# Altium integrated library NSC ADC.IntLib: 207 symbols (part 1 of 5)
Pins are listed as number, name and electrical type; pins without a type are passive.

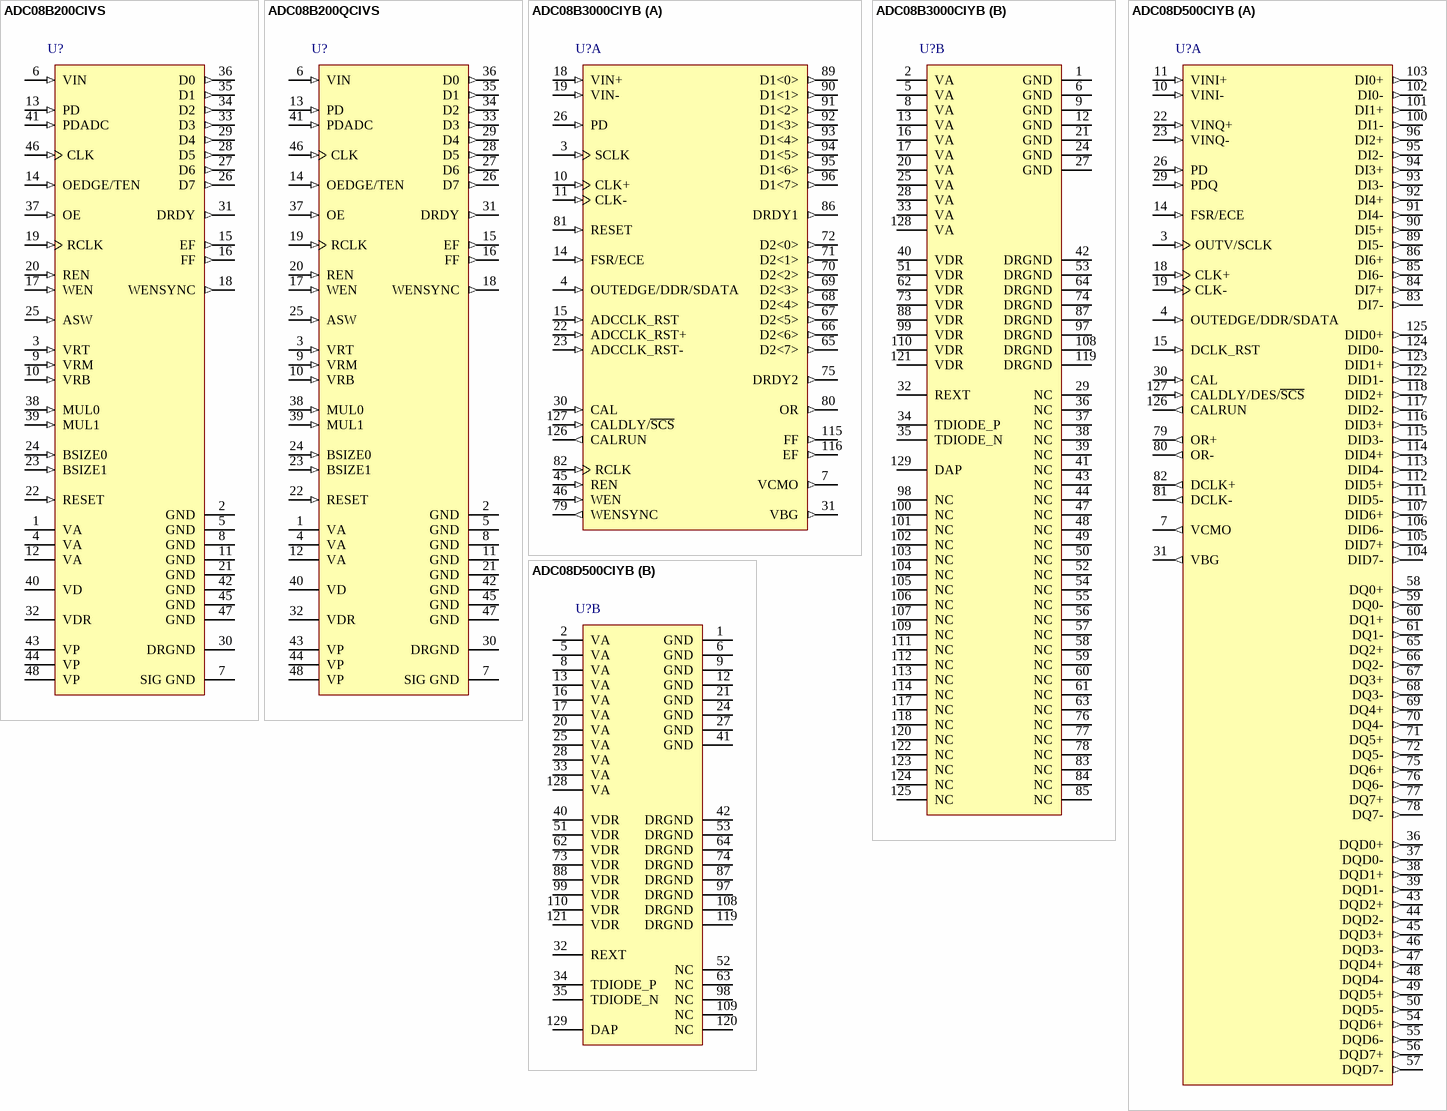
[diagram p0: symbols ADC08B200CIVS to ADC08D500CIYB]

## ADC08B200CIVS
designator U?
8-Bit, 200 MSPS A/D Converter with Capture Buffer; PartNumber: ADC08B200CIVS; Manufacturer: National Semiconductor; CompType: ADC IC; PackageTopMarking: NSUZXYTT*DC08B200*CIVS; PowerWise: N
footprint VBC48A_N (Thin QFP, 48-Leads, Body 7x7mm, Pitch 0.5mm, IPC Medium Density)
footprint VBC48A_L (Thin QFP, 48-Leads, Body 7x7mm, Pitch 0.5mm, IPC High Density)
footprint VBC48A_M (Thin QFP, 48-Leads, Body 7x7mm, Pitch 0.5mm, IPC Low Density)
pins: 1 VA (power), 2 GND (power), 3 VRT (in), 4 VA (power), 5 GND (power), 6 VIN (in), 7 SIG GND (power), 8 GND (power), 9 VRM (in), 10 VRB (in), 11 GND (power), 12 VA (power), 13 PD (in), 14 OEDGE/TEN (in), 15 EF (out), 16 FF (out), 17 WEN (in), 18 WENSYNC (out), 19 RCLK (in), 20 REN (in), 21 GND (power), 22 RESET (in), 23 BSIZE1 (in), 24 BSIZE0 (in), 25 ASW (in), 26 D7 (out), 27 D6 (out), 28 D5 (out), 29 D4 (out), 30 DRGND (power), 31 DRDY (out), 32 VDR (power), 33 D3 (out), 34 D2 (out), 35 D1 (out), 36 D0 (out), 37 OE (in), 38 MUL0 (in), 39 MUL1 (in), 40 VD (power), 41 PDADC (in), 42 GND (power), 43 VP (power), 44 VP (power), 45 GND (power), 46 CLK (in), 47 GND (power), 48 VP (power)

## ADC08B200QCIVS
designator U?
8-Bit, 200 MSPS A/D Converter with Capture Buffer; PartNumber: ADC08B200QCIVS; Manufacturer: National Semiconductor; CompType: ADC IC; PackageTopMarking: NSUZXYTT*DC08B200*QCIVS; PowerWise: N
footprint VBC48A_N (Thin QFP, 48-Leads, Body 7x7mm, Pitch 0.5mm, IPC Medium Density)
footprint VBC48A_L (Thin QFP, 48-Leads, Body 7x7mm, Pitch 0.5mm, IPC High Density)
footprint VBC48A_M (Thin QFP, 48-Leads, Body 7x7mm, Pitch 0.5mm, IPC Low Density)
pins: 1 VA (power), 2 GND (power), 3 VRT (in), 4 VA (power), 5 GND (power), 6 VIN (in), 7 SIG GND (power), 8 GND (power), 9 VRM (in), 10 VRB (in), 11 GND (power), 12 VA (power), 13 PD (in), 14 OEDGE/TEN (in), 15 EF (out), 16 FF (out), 17 WEN (in), 18 WENSYNC (out), 19 RCLK (in), 20 REN (in), 21 GND (power), 22 RESET (in), 23 BSIZE1 (in), 24 BSIZE0 (in), 25 ASW (in), 26 D7 (out), 27 D6 (out), 28 D5 (out), 29 D4 (out), 30 DRGND (power), 31 DRDY (out), 32 VDR (power), 33 D3 (out), 34 D2 (out), 35 D1 (out), 36 D0 (out), 37 OE (in), 38 MUL0 (in), 39 MUL1 (in), 40 VD (power), 41 PDADC (in), 42 GND (power), 43 VP (power), 44 VP (power), 45 GND (power), 46 CLK (in), 47 GND (power), 48 VP (power)

## ADC08B3000CIYB
designator U?
8-Bit, 3 GSPS, High Performance, Low Power A/D Converter with 4K Buffer; PartNumber: ADC08B3000CIYB; Manufacturer: National Semiconductor; CompType: ADC IC; PackageTopMarking: NSUZXYYTTE#*ADC08B3000*CIYB; PowerWise: Y
footprint VNX128A_N (Thin QFP, 128-Leads, Body 20x20mm, Pitch 0.5mm, Exposed Pad, IPC Medium Density)
footprint VNX128A_L (Thin QFP, 128-Leads, Body 20x20mm, Pitch 0.5mm, Exposed Pad, IPC High Density)
footprint VNX128A_M (Thin QFP, 128-Leads, Body 20x20mm, Pitch 0.5mm, Exposed Pad, IPC Low Density)
part A pins: 3 SCLK (in), 4 OUTEDGE/DDR/SDATA (in), 7 VCMO (out), 10 CLK+ (in), 11 CLK- (in), 14 FSR/ECE (in), 15 ADCCLK_RST (in), 18 VIN+ (in), 19 VIN- (in), 22 ADCCLK_RST+ (in), 23 ADCCLK_RST- (in), 26 PD (in), 30 CAL (in), 31 VBG (out), 45 REN (in), 46 WEN (in), 65 D2<7> (out), 66 D2<6> (out), 67 D2<5> (out), 68 D2<4> (out), 69 D2<3> (out), 70 D2<2> (out), 71 D2<1> (out), 72 D2<0> (out), 75 DRDY2 (out), 79 WENSYNC (out), 80 OR (out), 81 RESET (in), 82 RCLK (in), 86 DRDY1 (out), 89 D1<0> (out), 90 D1<1> (out), 91 D1<2> (out), 92 D1<3> (out), 93 D1<4> (out), 94 D1<5> (out), 95 D1<6> (out), 96 D1<7> (out), 115 FF (out), 116 EF (out), 126 CALRUN (out), 127 CALDLY/~{SCS} (in)
part B pins: 1 GND (power), 2 VA (power), 5 VA (power), 6 GND (power), 8 VA (power), 9 GND (power), 12 GND (power), 13 VA (power), 16 VA (power), 17 VA (power), 20 VA (power), 21 GND (power), 24 GND (power), 25 VA (power), 27 GND (power), 28 VA (power), 29 NC, 32 REXT, 33 VA (power), 34 TDIODE_P, 35 TDIODE_N, 36 NC, 37 NC, 38 NC, 39 NC, 40 VDR (power), 41 NC, 42 DRGND (power), 43 NC, 44 NC, 47 NC, 48 NC, 49 NC, 50 NC, 51 VDR (power), 52 NC, 53 DRGND (power), 54 NC, 55 NC, 56 NC, 57 NC, 58 NC, 59 NC, 60 NC, 61 NC, 62 VDR (power), 63 NC, 64 DRGND (power), 73 VDR (power), 74 DRGND (power), 76 NC, 77 NC, 78 NC, 83 NC, 84 NC, 85 NC, 87 DRGND (power), 88 VDR (power), 97 DRGND (power), 98 NC, 99 VDR (power), 100 NC, 101 NC, 102 NC, 103 NC, 104 NC, 105 NC, 106 NC, 107 NC, 108 DRGND (power), 109 NC, 110 VDR (power), 111 NC, 112 NC, 113 NC, 114 NC, 117 NC, 118 NC, 119 DRGND (power), 120 NC, 121 VDR (power), 122 NC, 123 NC, 124 NC, 125 NC, 128 VA (power), 129 DAP (power)

## ADC08D500CIYB
designator U?
High Performance, Low Power, Dual 8-Bit, 500 MSPS A/D Converter; PartNumber: ADC08D500CIYB; Manufacturer: National Semiconductor; CompType: ADC IC; PackageTopMarking: NSUZXYYTTE#*ADC08D500*CIYB; PowerWise: Y
footprint VNX128A_N (Thin QFP, 128-Leads, Body 20x20mm, Pitch 0.5mm, Exposed Pad, IPC Medium Density)
footprint VNX128A_L (Thin QFP, 128-Leads, Body 20x20mm, Pitch 0.5mm, Exposed Pad, IPC High Density)
footprint VNX128A_M (Thin QFP, 128-Leads, Body 20x20mm, Pitch 0.5mm, Exposed Pad, IPC Low Density)
part A pins: 3 OUTV/SCLK (in), 4 OUTEDGE/DDR/SDATA (in), 7 VCMO (out), 10 VINI- (in), 11 VINI+ (in), 14 FSR/ECE (in), 15 DCLK_RST (in), 18 CLK+ (in), 19 CLK- (in), 22 VINQ+ (in), 23 VINQ- (in), 26 PD (in), 29 PDQ (in), 30 CAL (in), 31 VBG (out), 36 DQD0+ (out), 37 DQD0- (out), 38 DQD1+ (out), 39 DQD1- (out), 43 DQD2+ (out), 44 DQD2- (out), 45 DQD3+ (out), 46 DQD3- (out), 47 DQD4+ (out), 48 DQD4- (out), 49 DQD5+ (out), 50 DQD5- (out), 54 DQD6+ (out), 55 DQD6- (out), 56 DQD7+ (out), 57 DQD7- (out), 58 DQ0+ (out), 59 DQ0- (out), 60 DQ1+ (out), 61 DQ1- (out), 65 DQ2+ (out), 66 DQ2- (out), 67 DQ3+ (out), 68 DQ3- (out), 69 DQ4+ (out), 70 DQ4- (out), 71 DQ5+ (out), 72 DQ5- (out), 75 DQ6+ (out), 76 DQ6- (out), 77 DQ7+ (out), 78 DQ7- (out), 79 OR+ (out), 80 OR- (out), 81 DCLK- (out), 82 DCLK+ (out), 83 DI7- (out), 84 DI7+ (out), 85 DI6- (out), 86 DI6+ (out), 89 DI5- (out), 90 DI5+ (out), 91 DI4- (out), 92 DI4+ (out), 93 DI3- (out), 94 DI3+ (out), 95 DI2- (out), 96 DI2+ (out), 100 DI1- (out), 101 DI1+ (out), 102 DI0- (out), 103 DI0+ (out), 104 DID7- (out), 105 DID7+ (out), 106 DID6- (out), 107 DID6+ (out), 111 DID5- (out), 112 DID5+ (out), 113 DID4- (out), 114 DID4+ (out), 115 DID3- (out), 116 DID3+ (out), 117 DID2- (out), 118 DID2+ (out), 122 DID1- (out), 123 DID1+ (out), 124 DID0- (out), 125 DID0+ (out), 126 CALRUN (out), 127 CALDLY/DES/~{SCS} (in)
part B pins: 1 GND (power), 2 VA (power), 5 VA (power), 6 GND (power), 8 VA (power), 9 GND (power), 12 GND (power), 13 VA (power), 16 VA (power), 17 VA (power), 20 VA (power), 21 GND (power), 24 GND (power), 25 VA (power), 27 GND (power), 28 VA (power), 32 REXT, 33 VA (power), 34 TDIODE_P, 35 TDIODE_N, 40 VDR (power), 41 GND (power), 42 DRGND (power), 51 VDR (power), 52 NC, 53 DRGND (power), 62 VDR (power), 63 NC, 64 DRGND (power), 73 VDR (power), 74 DRGND (power), 87 DRGND (power), 88 VDR (power), 97 DRGND (power), 98 NC, 99 VDR (power), 108 DRGND (power), 109 NC, 110 VDR (power), 119 DRGND (power), 120 NC, 121 VDR (power), 128 VA (power), 129 DAP (power)

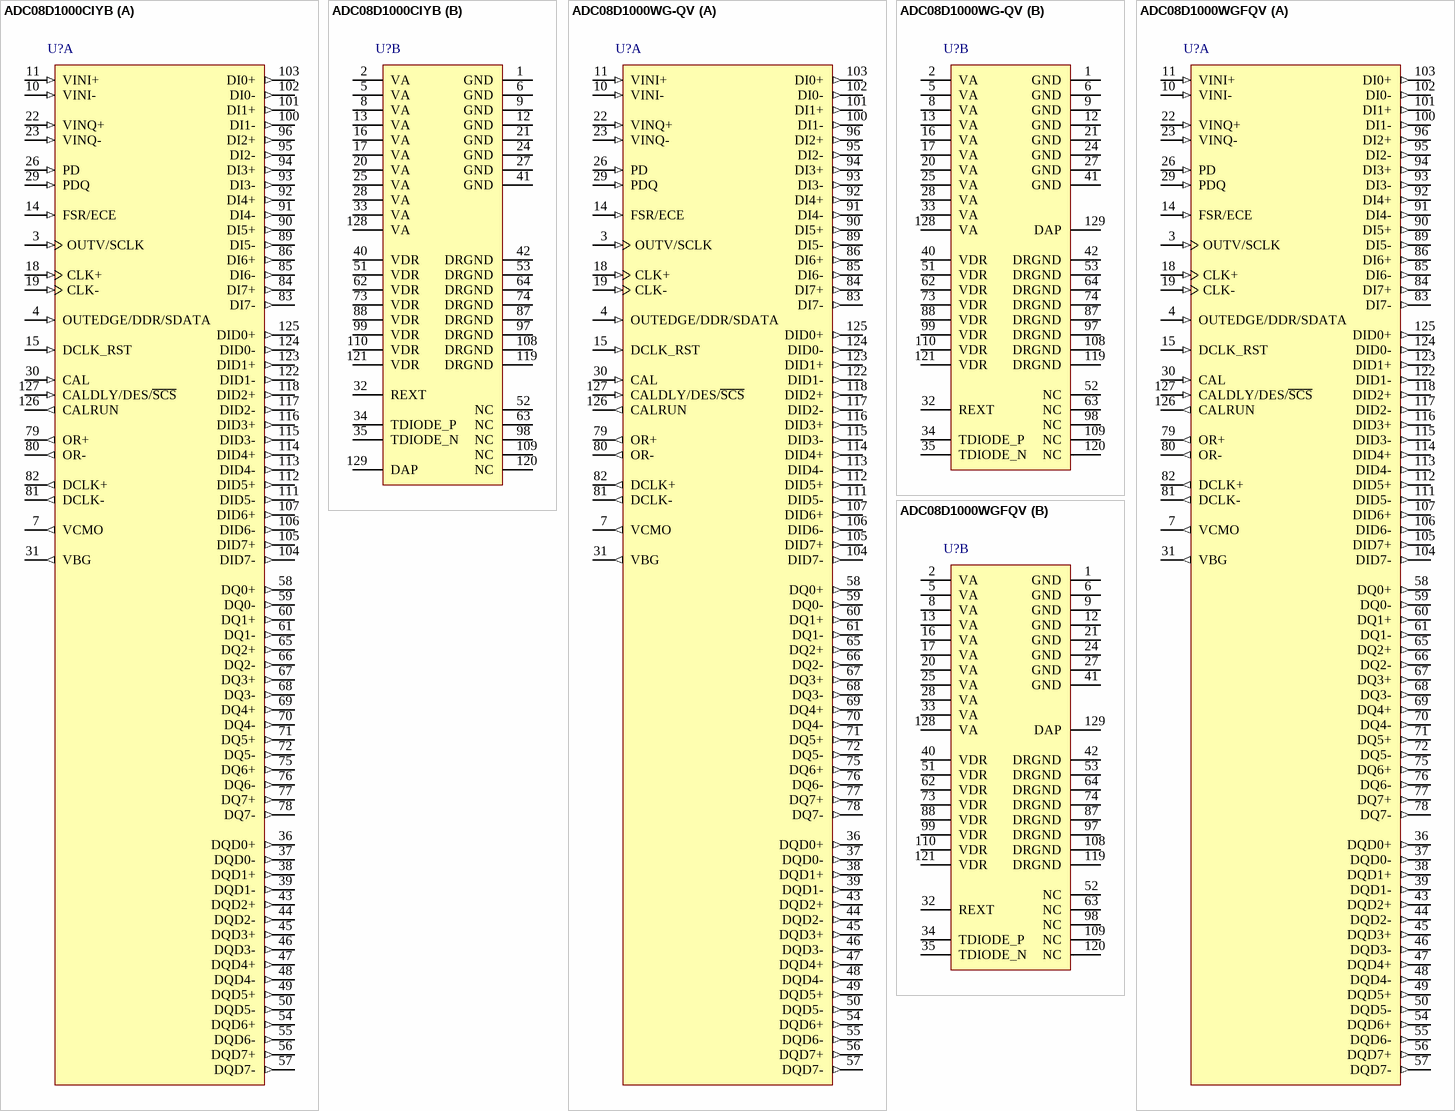
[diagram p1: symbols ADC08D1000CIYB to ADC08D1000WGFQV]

## ADC08D1000CIYB
designator U?
High Performance, Low Power, Dual 8-Bit, 1 GSPS A/D Converter; PartNumber: ADC08D1000CIYB; Manufacturer: National Semiconductor; CompType: ADC IC; PackageTopMarking: NSUZXYYTTE#*ADC08D1000*CIYB; PowerWise: Y
footprint VNX128A_N (Thin QFP, 128-Leads, Body 20x20mm, Pitch 0.5mm, Exposed Pad, IPC Medium Density)
footprint VNX128A_L (Thin QFP, 128-Leads, Body 20x20mm, Pitch 0.5mm, Exposed Pad, IPC High Density)
footprint VNX128A_M (Thin QFP, 128-Leads, Body 20x20mm, Pitch 0.5mm, Exposed Pad, IPC Low Density)
part A pins: 3 OUTV/SCLK (in), 4 OUTEDGE/DDR/SDATA (in), 7 VCMO (out), 10 VINI- (in), 11 VINI+ (in), 14 FSR/ECE (in), 15 DCLK_RST (in), 18 CLK+ (in), 19 CLK- (in), 22 VINQ+ (in), 23 VINQ- (in), 26 PD (in), 29 PDQ (in), 30 CAL (in), 31 VBG (out), 36 DQD0+ (out), 37 DQD0- (out), 38 DQD1+ (out), 39 DQD1- (out), 43 DQD2+ (out), 44 DQD2- (out), 45 DQD3+ (out), 46 DQD3- (out), 47 DQD4+ (out), 48 DQD4- (out), 49 DQD5+ (out), 50 DQD5- (out), 54 DQD6+ (out), 55 DQD6- (out), 56 DQD7+ (out), 57 DQD7- (out), 58 DQ0+ (out), 59 DQ0- (out), 60 DQ1+ (out), 61 DQ1- (out), 65 DQ2+ (out), 66 DQ2- (out), 67 DQ3+ (out), 68 DQ3- (out), 69 DQ4+ (out), 70 DQ4- (out), 71 DQ5+ (out), 72 DQ5- (out), 75 DQ6+ (out), 76 DQ6- (out), 77 DQ7+ (out), 78 DQ7- (out), 79 OR+ (out), 80 OR- (out), 81 DCLK- (out), 82 DCLK+ (out), 83 DI7- (out), 84 DI7+ (out), 85 DI6- (out), 86 DI6+ (out), 89 DI5- (out), 90 DI5+ (out), 91 DI4- (out), 92 DI4+ (out), 93 DI3- (out), 94 DI3+ (out), 95 DI2- (out), 96 DI2+ (out), 100 DI1- (out), 101 DI1+ (out), 102 DI0- (out), 103 DI0+ (out), 104 DID7- (out), 105 DID7+ (out), 106 DID6- (out), 107 DID6+ (out), 111 DID5- (out), 112 DID5+ (out), 113 DID4- (out), 114 DID4+ (out), 115 DID3- (out), 116 DID3+ (out), 117 DID2- (out), 118 DID2+ (out), 122 DID1- (out), 123 DID1+ (out), 124 DID0- (out), 125 DID0+ (out), 126 CALRUN (out), 127 CALDLY/DES/~{SCS} (in)
part B pins: 1 GND (power), 2 VA (power), 5 VA (power), 6 GND (power), 8 VA (power), 9 GND (power), 12 GND (power), 13 VA (power), 16 VA (power), 17 VA (power), 20 VA (power), 21 GND (power), 24 GND (power), 25 VA (power), 27 GND (power), 28 VA (power), 32 REXT, 33 VA (power), 34 TDIODE_P, 35 TDIODE_N, 40 VDR (power), 41 GND (power), 42 DRGND (power), 51 VDR (power), 52 NC, 53 DRGND (power), 62 VDR (power), 63 NC, 64 DRGND (power), 73 VDR (power), 74 DRGND (power), 87 DRGND (power), 88 VDR (power), 97 DRGND (power), 98 NC, 99 VDR (power), 108 DRGND (power), 109 NC, 110 VDR (power), 119 DRGND (power), 120 NC, 121 VDR (power), 128 VA (power), 129 DAP (power)

## ADC08D1000WG-QV
designator U?
High Performance, Low Power, Dual 8-Bit, 1 GSPS A/D Converter; PartNumber: ADC08D1000WG-QV; Manufacturer: National Semiconductor; CompType: ADC IC; PackageTopMarking: NSZSSXXYYA*ADC08D1000*WG-QV 5962-*0520601VZC Q; PowerWise: N
footprint EM128A_N (CQFP, 128-Leads, Body 19.6x19.6mm; Pitch 0.508mm, Gullwing Leadform, IPC Medium Density)
footprint EM128A_L (CQFP, 128-Leads, Body 19.6x19.6mm; Pitch 0.508mm, Gullwing Leadform, IPC High Density)
footprint EM128A_M (CQFP, 128-Leads, Body 19.6x19.6mm; Pitch 0.508mm, Gullwing Leadform, IPC Low Density)
part A pins: 3 OUTV/SCLK (in), 4 OUTEDGE/DDR/SDATA (in), 7 VCMO (out), 10 VINI- (in), 11 VINI+ (in), 14 FSR/ECE (in), 15 DCLK_RST (in), 18 CLK+ (in), 19 CLK- (in), 22 VINQ+ (in), 23 VINQ- (in), 26 PD (in), 29 PDQ (in), 30 CAL (in), 31 VBG (out), 36 DQD0+ (out), 37 DQD0- (out), 38 DQD1+ (out), 39 DQD1- (out), 43 DQD2+ (out), 44 DQD2- (out), 45 DQD3+ (out), 46 DQD3- (out), 47 DQD4+ (out), 48 DQD4- (out), 49 DQD5+ (out), 50 DQD5- (out), 54 DQD6+ (out), 55 DQD6- (out), 56 DQD7+ (out), 57 DQD7- (out), 58 DQ0+ (out), 59 DQ0- (out), 60 DQ1+ (out), 61 DQ1- (out), 65 DQ2+ (out), 66 DQ2- (out), 67 DQ3+ (out), 68 DQ3- (out), 69 DQ4+ (out), 70 DQ4- (out), 71 DQ5+ (out), 72 DQ5- (out), 75 DQ6+ (out), 76 DQ6- (out), 77 DQ7+ (out), 78 DQ7- (out), 79 OR+ (out), 80 OR- (out), 81 DCLK- (out), 82 DCLK+ (out), 83 DI7- (out), 84 DI7+ (out), 85 DI6- (out), 86 DI6+ (out), 89 DI5- (out), 90 DI5+ (out), 91 DI4- (out), 92 DI4+ (out), 93 DI3- (out), 94 DI3+ (out), 95 DI2- (out), 96 DI2+ (out), 100 DI1- (out), 101 DI1+ (out), 102 DI0- (out), 103 DI0+ (out), 104 DID7- (out), 105 DID7+ (out), 106 DID6- (out), 107 DID6+ (out), 111 DID5- (out), 112 DID5+ (out), 113 DID4- (out), 114 DID4+ (out), 115 DID3- (out), 116 DID3+ (out), 117 DID2- (out), 118 DID2+ (out), 122 DID1- (out), 123 DID1+ (out), 124 DID0- (out), 125 DID0+ (out), 126 CALRUN (out), 127 CALDLY/DES/~{SCS} (in)
part B pins: 1 GND (power), 2 VA (power), 5 VA (power), 6 GND (power), 8 VA (power), 9 GND (power), 12 GND (power), 13 VA (power), 16 VA (power), 17 VA (power), 20 VA (power), 21 GND (power), 24 GND (power), 25 VA (power), 27 GND (power), 28 VA (power), 32 REXT, 33 VA (power), 34 TDIODE_P, 35 TDIODE_N, 40 VDR (power), 41 GND (power), 42 DRGND (power), 51 VDR (power), 52 NC, 53 DRGND (power), 62 VDR (power), 63 NC, 64 DRGND (power), 73 VDR (power), 74 DRGND (power), 87 DRGND (power), 88 VDR (power), 97 DRGND (power), 98 NC, 99 VDR (power), 108 DRGND (power), 109 NC, 110 VDR (power), 119 DRGND (power), 120 NC, 121 VDR (power), 128 VA (power), 129 DAP (power)

## ADC08D1000WGFQV
designator U?
High Performance, Low Power, Dual 8-Bit, 1 GSPS A/D Converter; PartNumber: ADC08D1000WGFQV; Manufacturer: National Semiconductor; CompType: ADC IC; PackageTopMarking: NSZSSXXYYA*ADC08D1000*WGFQV 5962F*0520601VZC Q; PowerWise: N
footprint EM128A_N (CQFP, 128-Leads, Body 19.6x19.6mm; Pitch 0.508mm, Gullwing Leadform, IPC Medium Density)
footprint EM128A_L (CQFP, 128-Leads, Body 19.6x19.6mm; Pitch 0.508mm, Gullwing Leadform, IPC High Density)
footprint EM128A_M (CQFP, 128-Leads, Body 19.6x19.6mm; Pitch 0.508mm, Gullwing Leadform, IPC Low Density)
part A pins: 3 OUTV/SCLK (in), 4 OUTEDGE/DDR/SDATA (in), 7 VCMO (out), 10 VINI- (in), 11 VINI+ (in), 14 FSR/ECE (in), 15 DCLK_RST (in), 18 CLK+ (in), 19 CLK- (in), 22 VINQ+ (in), 23 VINQ- (in), 26 PD (in), 29 PDQ (in), 30 CAL (in), 31 VBG (out), 36 DQD0+ (out), 37 DQD0- (out), 38 DQD1+ (out), 39 DQD1- (out), 43 DQD2+ (out), 44 DQD2- (out), 45 DQD3+ (out), 46 DQD3- (out), 47 DQD4+ (out), 48 DQD4- (out), 49 DQD5+ (out), 50 DQD5- (out), 54 DQD6+ (out), 55 DQD6- (out), 56 DQD7+ (out), 57 DQD7- (out), 58 DQ0+ (out), 59 DQ0- (out), 60 DQ1+ (out), 61 DQ1- (out), 65 DQ2+ (out), 66 DQ2- (out), 67 DQ3+ (out), 68 DQ3- (out), 69 DQ4+ (out), 70 DQ4- (out), 71 DQ5+ (out), 72 DQ5- (out), 75 DQ6+ (out), 76 DQ6- (out), 77 DQ7+ (out), 78 DQ7- (out), 79 OR+ (out), 80 OR- (out), 81 DCLK- (out), 82 DCLK+ (out), 83 DI7- (out), 84 DI7+ (out), 85 DI6- (out), 86 DI6+ (out), 89 DI5- (out), 90 DI5+ (out), 91 DI4- (out), 92 DI4+ (out), 93 DI3- (out), 94 DI3+ (out), 95 DI2- (out), 96 DI2+ (out), 100 DI1- (out), 101 DI1+ (out), 102 DI0- (out), 103 DI0+ (out), 104 DID7- (out), 105 DID7+ (out), 106 DID6- (out), 107 DID6+ (out), 111 DID5- (out), 112 DID5+ (out), 113 DID4- (out), 114 DID4+ (out), 115 DID3- (out), 116 DID3+ (out), 117 DID2- (out), 118 DID2+ (out), 122 DID1- (out), 123 DID1+ (out), 124 DID0- (out), 125 DID0+ (out), 126 CALRUN (out), 127 CALDLY/DES/~{SCS} (in)
part B pins: 1 GND (power), 2 VA (power), 5 VA (power), 6 GND (power), 8 VA (power), 9 GND (power), 12 GND (power), 13 VA (power), 16 VA (power), 17 VA (power), 20 VA (power), 21 GND (power), 24 GND (power), 25 VA (power), 27 GND (power), 28 VA (power), 32 REXT, 33 VA (power), 34 TDIODE_P, 35 TDIODE_N, 40 VDR (power), 41 GND (power), 42 DRGND (power), 51 VDR (power), 52 NC, 53 DRGND (power), 62 VDR (power), 63 NC, 64 DRGND (power), 73 VDR (power), 74 DRGND (power), 87 DRGND (power), 88 VDR (power), 97 DRGND (power), 98 NC, 99 VDR (power), 108 DRGND (power), 109 NC, 110 VDR (power), 119 DRGND (power), 120 NC, 121 VDR (power), 128 VA (power), 129 DAP (power)

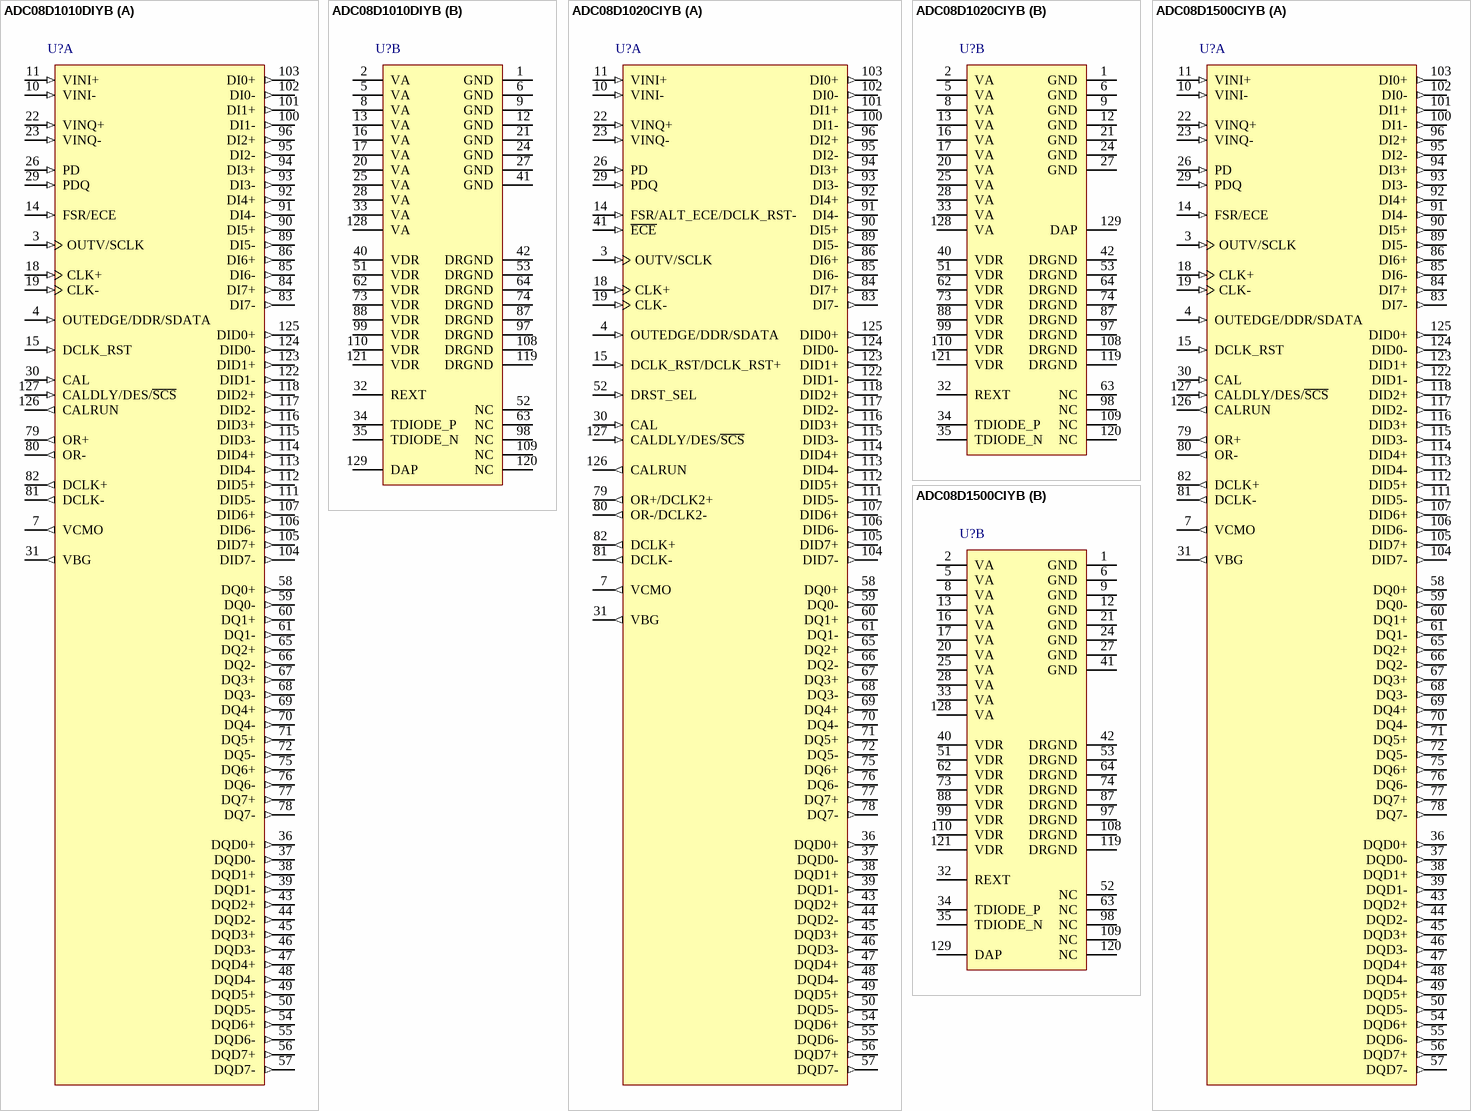
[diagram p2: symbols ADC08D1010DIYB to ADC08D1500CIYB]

## ADC08D1010DIYB
designator U?
High Performance, Low Power, Dual 8-Bit, 1 GSPS A/D Converter; PartNumber: ADC08D1010DIYB; Manufacturer: National Semiconductor; CompType: ADC IC; PackageTopMarking: NSUZXYYTTE#*ADC08D1010*DIYB
footprint VNX128A_N (Thin QFP, 128-Leads, Body 20x20mm, Pitch 0.5mm, Exposed Pad, IPC Medium Density)
footprint VNX128A_L (Thin QFP, 128-Leads, Body 20x20mm, Pitch 0.5mm, Exposed Pad, IPC High Density)
footprint VNX128A_M (Thin QFP, 128-Leads, Body 20x20mm, Pitch 0.5mm, Exposed Pad, IPC Low Density)
part A pins: 3 OUTV/SCLK (in), 4 OUTEDGE/DDR/SDATA (in), 7 VCMO (out), 10 VINI- (in), 11 VINI+ (in), 14 FSR/ECE (in), 15 DCLK_RST (in), 18 CLK+ (in), 19 CLK- (in), 22 VINQ+ (in), 23 VINQ- (in), 26 PD (in), 29 PDQ (in), 30 CAL (in), 31 VBG (out), 36 DQD0+ (out), 37 DQD0- (out), 38 DQD1+ (out), 39 DQD1- (out), 43 DQD2+ (out), 44 DQD2- (out), 45 DQD3+ (out), 46 DQD3- (out), 47 DQD4+ (out), 48 DQD4- (out), 49 DQD5+ (out), 50 DQD5- (out), 54 DQD6+ (out), 55 DQD6- (out), 56 DQD7+ (out), 57 DQD7- (out), 58 DQ0+ (out), 59 DQ0- (out), 60 DQ1+ (out), 61 DQ1- (out), 65 DQ2+ (out), 66 DQ2- (out), 67 DQ3+ (out), 68 DQ3- (out), 69 DQ4+ (out), 70 DQ4- (out), 71 DQ5+ (out), 72 DQ5- (out), 75 DQ6+ (out), 76 DQ6- (out), 77 DQ7+ (out), 78 DQ7- (out), 79 OR+ (out), 80 OR- (out), 81 DCLK- (out), 82 DCLK+ (out), 83 DI7- (out), 84 DI7+ (out), 85 DI6- (out), 86 DI6+ (out), 89 DI5- (out), 90 DI5+ (out), 91 DI4- (out), 92 DI4+ (out), 93 DI3- (out), 94 DI3+ (out), 95 DI2- (out), 96 DI2+ (out), 100 DI1- (out), 101 DI1+ (out), 102 DI0- (out), 103 DI0+ (out), 104 DID7- (out), 105 DID7+ (out), 106 DID6- (out), 107 DID6+ (out), 111 DID5- (out), 112 DID5+ (out), 113 DID4- (out), 114 DID4+ (out), 115 DID3- (out), 116 DID3+ (out), 117 DID2- (out), 118 DID2+ (out), 122 DID1- (out), 123 DID1+ (out), 124 DID0- (out), 125 DID0+ (out), 126 CALRUN (out), 127 CALDLY/DES/~{SCS} (in)
part B pins: 1 GND (power), 2 VA (power), 5 VA (power), 6 GND (power), 8 VA (power), 9 GND (power), 12 GND (power), 13 VA (power), 16 VA (power), 17 VA (power), 20 VA (power), 21 GND (power), 24 GND (power), 25 VA (power), 27 GND (power), 28 VA (power), 32 REXT, 33 VA (power), 34 TDIODE_P, 35 TDIODE_N, 40 VDR (power), 41 GND (power), 42 DRGND (power), 51 VDR (power), 52 NC, 53 DRGND (power), 62 VDR (power), 63 NC, 64 DRGND (power), 73 VDR (power), 74 DRGND (power), 87 DRGND (power), 88 VDR (power), 97 DRGND (power), 98 NC, 99 VDR (power), 108 DRGND (power), 109 NC, 110 VDR (power), 119 DRGND (power), 120 NC, 121 VDR (power), 128 VA (power), 129 DAP (power)

## ADC08D1020CIYB
designator U?
Low Power, Dual 8-Bit, 1.0 GSPS A/D Converter; PartNumber: ADC08D1020CIYB; Manufacturer: National Semiconductor; CompType: ADC IC; PackageTopMarking: NSUZXYYTTE#*ADC08D1020*CIYB; PowerWise: Y
footprint VNX128A_N (Thin QFP, 128-Leads, Body 20x20mm, Pitch 0.5mm, Exposed Pad, IPC Medium Density)
footprint VNX128A_L (Thin QFP, 128-Leads, Body 20x20mm, Pitch 0.5mm, Exposed Pad, IPC High Density)
footprint VNX128A_M (Thin QFP, 128-Leads, Body 20x20mm, Pitch 0.5mm, Exposed Pad, IPC Low Density)
part A pins: 3 OUTV/SCLK (in), 4 OUTEDGE/DDR/SDATA (in), 7 VCMO (out), 10 VINI- (in), 11 VINI+ (in), 14 FSR/ALT_ECE/DCLK_RST- (in), 15 DCLK_RST/DCLK_RST+ (in), 18 CLK+ (in), 19 CLK- (in), 22 VINQ+ (in), 23 VINQ- (in), 26 PD (in), 29 PDQ (in), 30 CAL (in), 31 VBG (out), 36 DQD0+ (out), 37 DQD0- (out), 38 DQD1+ (out), 39 DQD1- (out), 41 ~{ECE} (in), 43 DQD2+ (out), 44 DQD2- (out), 45 DQD3+ (out), 46 DQD3- (out), 47 DQD4+ (out), 48 DQD4- (out), 49 DQD5+ (out), 50 DQD5- (out), 52 DRST_SEL (in), 54 DQD6+ (out), 55 DQD6- (out), 56 DQD7+ (out), 57 DQD7- (out), 58 DQ0+ (out), 59 DQ0- (out), 60 DQ1+ (out), 61 DQ1- (out), 65 DQ2+ (out), 66 DQ2- (out), 67 DQ3+ (out), 68 DQ3- (out), 69 DQ4+ (out), 70 DQ4- (out), 71 DQ5+ (out), 72 DQ5- (out), 75 DQ6+ (out), 76 DQ6- (out), 77 DQ7+ (out), 78 DQ7- (out), 79 OR+/DCLK2+ (out), 80 OR-/DCLK2- (out), 81 DCLK- (out), 82 DCLK+ (out), 83 DI7- (out), 84 DI7+ (out), 85 DI6- (out), 86 DI6+ (out), 89 DI5- (out), 90 DI5+ (out), 91 DI4- (out), 92 DI4+ (out), 93 DI3- (out), 94 DI3+ (out), 95 DI2- (out), 96 DI2+ (out), 100 DI1- (out), 101 DI1+ (out), 102 DI0- (out), 103 DI0+ (out), 104 DID7- (out), 105 DID7+ (out), 106 DID6- (out), 107 DID6+ (out), 111 DID5- (out), 112 DID5+ (out), 113 DID4- (out), 114 DID4+ (out), 115 DID3- (out), 116 DID3+ (out), 117 DID2- (out), 118 DID2+ (out), 122 DID1- (out), 123 DID1+ (out), 124 DID0- (out), 125 DID0+ (out), 126 CALRUN (out), 127 CALDLY/DES/~{SCS} (in)
part B pins: 1 GND (power), 2 VA (power), 5 VA (power), 6 GND (power), 8 VA (power), 9 GND (power), 12 GND (power), 13 VA (power), 16 VA (power), 17 VA (power), 20 VA (power), 21 GND (power), 24 GND (power), 25 VA (power), 27 GND (power), 28 VA (power), 32 REXT, 33 VA (power), 34 TDIODE_P, 35 TDIODE_N, 40 VDR (power), 42 DRGND (power), 51 VDR (power), 53 DRGND (power), 62 VDR (power), 63 NC, 64 DRGND (power), 73 VDR (power), 74 DRGND (power), 87 DRGND (power), 88 VDR (power), 97 DRGND (power), 98 NC, 99 VDR (power), 108 DRGND (power), 109 NC, 110 VDR (power), 119 DRGND (power), 120 NC, 121 VDR (power), 128 VA (power), 129 DAP (power)

## ADC08D1500CIYB
designator U?
High Performance, Low Power, Dual 8-Bit, 1.5 GSPS A/D Converter; PartNumber: ADC08D1500CIYB; Manufacturer: National Semiconductor; CompType: ADC IC; PackageTopMarking: NSUZXYYTTE#*ADC08D1500*CIYB; PowerWise: Y
footprint VNX128A_N (Thin QFP, 128-Leads, Body 20x20mm, Pitch 0.5mm, Exposed Pad, IPC Medium Density)
footprint VNX128A_L (Thin QFP, 128-Leads, Body 20x20mm, Pitch 0.5mm, Exposed Pad, IPC High Density)
footprint VNX128A_M (Thin QFP, 128-Leads, Body 20x20mm, Pitch 0.5mm, Exposed Pad, IPC Low Density)
part A pins: 3 OUTV/SCLK (in), 4 OUTEDGE/DDR/SDATA (in), 7 VCMO (out), 10 VINI- (in), 11 VINI+ (in), 14 FSR/ECE (in), 15 DCLK_RST (in), 18 CLK+ (in), 19 CLK- (in), 22 VINQ+ (in), 23 VINQ- (in), 26 PD (in), 29 PDQ (in), 30 CAL (in), 31 VBG (out), 36 DQD0+ (out), 37 DQD0- (out), 38 DQD1+ (out), 39 DQD1- (out), 43 DQD2+ (out), 44 DQD2- (out), 45 DQD3+ (out), 46 DQD3- (out), 47 DQD4+ (out), 48 DQD4- (out), 49 DQD5+ (out), 50 DQD5- (out), 54 DQD6+ (out), 55 DQD6- (out), 56 DQD7+ (out), 57 DQD7- (out), 58 DQ0+ (out), 59 DQ0- (out), 60 DQ1+ (out), 61 DQ1- (out), 65 DQ2+ (out), 66 DQ2- (out), 67 DQ3+ (out), 68 DQ3- (out), 69 DQ4+ (out), 70 DQ4- (out), 71 DQ5+ (out), 72 DQ5- (out), 75 DQ6+ (out), 76 DQ6- (out), 77 DQ7+ (out), 78 DQ7- (out), 79 OR+ (out), 80 OR- (out), 81 DCLK- (out), 82 DCLK+ (out), 83 DI7- (out), 84 DI7+ (out), 85 DI6- (out), 86 DI6+ (out), 89 DI5- (out), 90 DI5+ (out), 91 DI4- (out), 92 DI4+ (out), 93 DI3- (out), 94 DI3+ (out), 95 DI2- (out), 96 DI2+ (out), 100 DI1- (out), 101 DI1+ (out), 102 DI0- (out), 103 DI0+ (out), 104 DID7- (out), 105 DID7+ (out), 106 DID6- (out), 107 DID6+ (out), 111 DID5- (out), 112 DID5+ (out), 113 DID4- (out), 114 DID4+ (out), 115 DID3- (out), 116 DID3+ (out), 117 DID2- (out), 118 DID2+ (out), 122 DID1- (out), 123 DID1+ (out), 124 DID0- (out), 125 DID0+ (out), 126 CALRUN (out), 127 CALDLY/DES/~{SCS} (in)
part B pins: 1 GND (power), 2 VA (power), 5 VA (power), 6 GND (power), 8 VA (power), 9 GND (power), 12 GND (power), 13 VA (power), 16 VA (power), 17 VA (power), 20 VA (power), 21 GND (power), 24 GND (power), 25 VA (power), 27 GND (power), 28 VA (power), 32 REXT, 33 VA (power), 34 TDIODE_P, 35 TDIODE_N, 40 VDR (power), 41 GND (power), 42 DRGND (power), 51 VDR (power), 52 NC, 53 DRGND (power), 62 VDR (power), 63 NC, 64 DRGND (power), 73 VDR (power), 74 DRGND (power), 87 DRGND (power), 88 VDR (power), 97 DRGND (power), 98 NC, 99 VDR (power), 108 DRGND (power), 109 NC, 110 VDR (power), 119 DRGND (power), 120 NC, 121 VDR (power), 128 VA (power), 129 DAP (power)

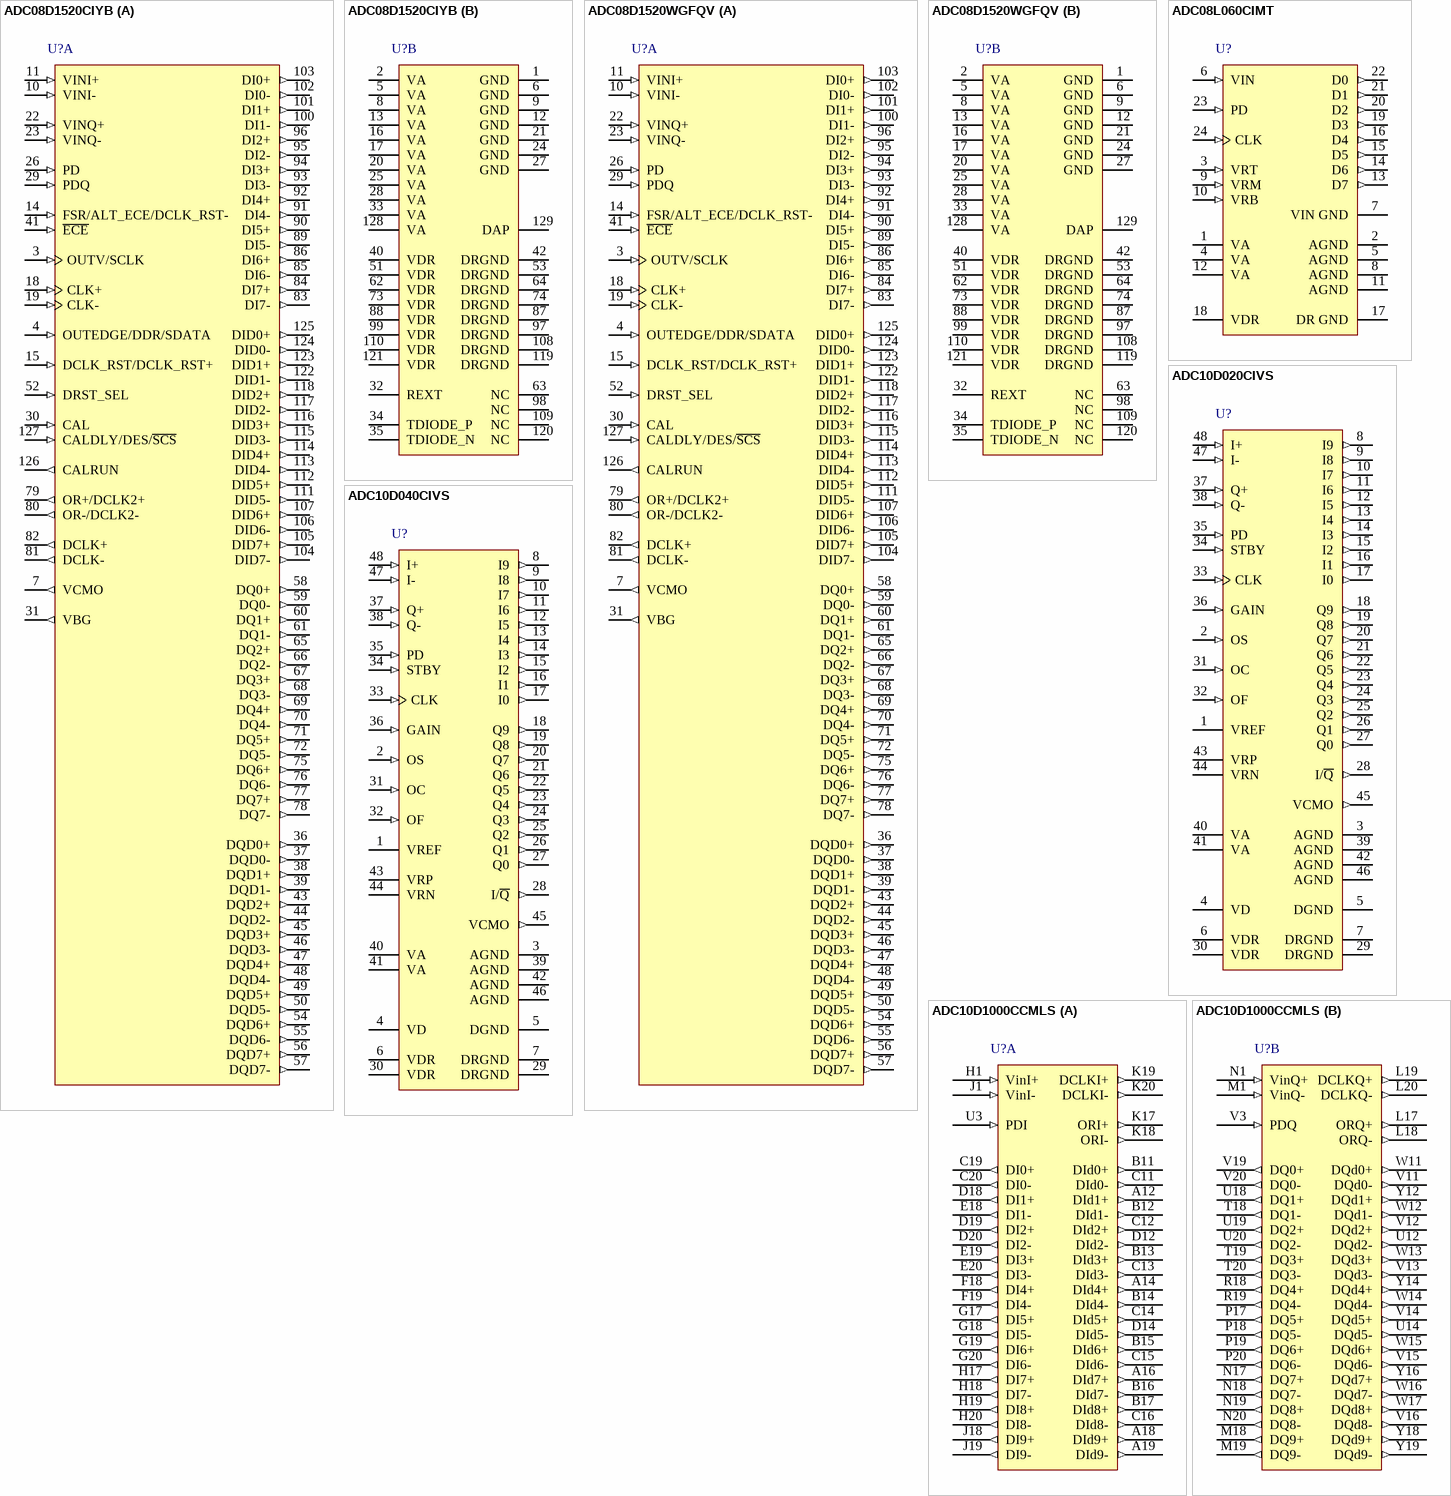
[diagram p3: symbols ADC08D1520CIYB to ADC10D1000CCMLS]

## ADC08D1520CIYB
designator U?
Low Power, 8-Bit, Dual 1.5 GSPS or Single 3.0 GSPS A/D Converter; PartNumber: ADC08D1520CIYB; Manufacturer: National Semiconductor; CompType: ADC IC; PackageTopMarking: NSUZXYYTTE#*ADC08D1520*CIYB; PowerWise: Y
footprint VNX128A_N (Thin QFP, 128-Leads, Body 20x20mm, Pitch 0.5mm, Exposed Pad, IPC Medium Density)
footprint VNX128A_L (Thin QFP, 128-Leads, Body 20x20mm, Pitch 0.5mm, Exposed Pad, IPC High Density)
footprint VNX128A_M (Thin QFP, 128-Leads, Body 20x20mm, Pitch 0.5mm, Exposed Pad, IPC Low Density)
part A pins: 3 OUTV/SCLK (in), 4 OUTEDGE/DDR/SDATA (in), 7 VCMO (out), 10 VINI- (in), 11 VINI+ (in), 14 FSR/ALT_ECE/DCLK_RST- (in), 15 DCLK_RST/DCLK_RST+ (in), 18 CLK+ (in), 19 CLK- (in), 22 VINQ+ (in), 23 VINQ- (in), 26 PD (in), 29 PDQ (in), 30 CAL (in), 31 VBG (out), 36 DQD0+ (out), 37 DQD0- (out), 38 DQD1+ (out), 39 DQD1- (out), 41 ~{ECE} (in), 43 DQD2+ (out), 44 DQD2- (out), 45 DQD3+ (out), 46 DQD3- (out), 47 DQD4+ (out), 48 DQD4- (out), 49 DQD5+ (out), 50 DQD5- (out), 52 DRST_SEL (in), 54 DQD6+ (out), 55 DQD6- (out), 56 DQD7+ (out), 57 DQD7- (out), 58 DQ0+ (out), 59 DQ0- (out), 60 DQ1+ (out), 61 DQ1- (out), 65 DQ2+ (out), 66 DQ2- (out), 67 DQ3+ (out), 68 DQ3- (out), 69 DQ4+ (out), 70 DQ4- (out), 71 DQ5+ (out), 72 DQ5- (out), 75 DQ6+ (out), 76 DQ6- (out), 77 DQ7+ (out), 78 DQ7- (out), 79 OR+/DCLK2+ (out), 80 OR-/DCLK2- (out), 81 DCLK- (out), 82 DCLK+ (out), 83 DI7- (out), 84 DI7+ (out), 85 DI6- (out), 86 DI6+ (out), 89 DI5- (out), 90 DI5+ (out), 91 DI4- (out), 92 DI4+ (out), 93 DI3- (out), 94 DI3+ (out), 95 DI2- (out), 96 DI2+ (out), 100 DI1- (out), 101 DI1+ (out), 102 DI0- (out), 103 DI0+ (out), 104 DID7- (out), 105 DID7+ (out), 106 DID6- (out), 107 DID6+ (out), 111 DID5- (out), 112 DID5+ (out), 113 DID4- (out), 114 DID4+ (out), 115 DID3- (out), 116 DID3+ (out), 117 DID2- (out), 118 DID2+ (out), 122 DID1- (out), 123 DID1+ (out), 124 DID0- (out), 125 DID0+ (out), 126 CALRUN (out), 127 CALDLY/DES/~{SCS} (in)
part B pins: 1 GND (power), 2 VA (power), 5 VA (power), 6 GND (power), 8 VA (power), 9 GND (power), 12 GND (power), 13 VA (power), 16 VA (power), 17 VA (power), 20 VA (power), 21 GND (power), 24 GND (power), 25 VA (power), 27 GND (power), 28 VA (power), 32 REXT, 33 VA (power), 34 TDIODE_P, 35 TDIODE_N, 40 VDR (power), 42 DRGND (power), 51 VDR (power), 53 DRGND (power), 62 VDR (power), 63 NC, 64 DRGND (power), 73 VDR (power), 74 DRGND (power), 87 DRGND (power), 88 VDR (power), 97 DRGND (power), 98 NC, 99 VDR (power), 108 DRGND (power), 109 NC, 110 VDR (power), 119 DRGND (power), 120 NC, 121 VDR (power), 128 VA (power), 129 DAP (power)

## ADC08D1520WGFQV
designator U?
Low Power, 8-Bit, Dual 1.5 GSPS or Single 3.0 GSPS A/D Converter; PartNumber: ADC08D1520WGFQV; Manufacturer: National Semiconductor; CompType: ADC IC; PackageTopMarking: NSZSSXXYYA*ADC08D1520*WGFQV 5962F*0721401VZC Q; PowerWise: N
footprint EM128A_N (CQFP, 128-Leads, Body 19.6x19.6mm; Pitch 0.508mm, Gullwing Leadform, IPC Medium Density)
footprint EM128A_L (CQFP, 128-Leads, Body 19.6x19.6mm; Pitch 0.508mm, Gullwing Leadform, IPC High Density)
footprint EM128A_M (CQFP, 128-Leads, Body 19.6x19.6mm; Pitch 0.508mm, Gullwing Leadform, IPC Low Density)
part A pins: 3 OUTV/SCLK (in), 4 OUTEDGE/DDR/SDATA (in), 7 VCMO (out), 10 VINI- (in), 11 VINI+ (in), 14 FSR/ALT_ECE/DCLK_RST- (in), 15 DCLK_RST/DCLK_RST+ (in), 18 CLK+ (in), 19 CLK- (in), 22 VINQ+ (in), 23 VINQ- (in), 26 PD (in), 29 PDQ (in), 30 CAL (in), 31 VBG (out), 36 DQD0+ (out), 37 DQD0- (out), 38 DQD1+ (out), 39 DQD1- (out), 41 ~{ECE} (in), 43 DQD2+ (out), 44 DQD2- (out), 45 DQD3+ (out), 46 DQD3- (out), 47 DQD4+ (out), 48 DQD4- (out), 49 DQD5+ (out), 50 DQD5- (out), 52 DRST_SEL (in), 54 DQD6+ (out), 55 DQD6- (out), 56 DQD7+ (out), 57 DQD7- (out), 58 DQ0+ (out), 59 DQ0- (out), 60 DQ1+ (out), 61 DQ1- (out), 65 DQ2+ (out), 66 DQ2- (out), 67 DQ3+ (out), 68 DQ3- (out), 69 DQ4+ (out), 70 DQ4- (out), 71 DQ5+ (out), 72 DQ5- (out), 75 DQ6+ (out), 76 DQ6- (out), 77 DQ7+ (out), 78 DQ7- (out), 79 OR+/DCLK2+ (out), 80 OR-/DCLK2- (out), 81 DCLK- (out), 82 DCLK+ (out), 83 DI7- (out), 84 DI7+ (out), 85 DI6- (out), 86 DI6+ (out), 89 DI5- (out), 90 DI5+ (out), 91 DI4- (out), 92 DI4+ (out), 93 DI3- (out), 94 DI3+ (out), 95 DI2- (out), 96 DI2+ (out), 100 DI1- (out), 101 DI1+ (out), 102 DI0- (out), 103 DI0+ (out), 104 DID7- (out), 105 DID7+ (out), 106 DID6- (out), 107 DID6+ (out), 111 DID5- (out), 112 DID5+ (out), 113 DID4- (out), 114 DID4+ (out), 115 DID3- (out), 116 DID3+ (out), 117 DID2- (out), 118 DID2+ (out), 122 DID1- (out), 123 DID1+ (out), 124 DID0- (out), 125 DID0+ (out), 126 CALRUN (out), 127 CALDLY/DES/~{SCS} (in)
part B pins: 1 GND (power), 2 VA (power), 5 VA (power), 6 GND (power), 8 VA (power), 9 GND (power), 12 GND (power), 13 VA (power), 16 VA (power), 17 VA (power), 20 VA (power), 21 GND (power), 24 GND (power), 25 VA (power), 27 GND (power), 28 VA (power), 32 REXT, 33 VA (power), 34 TDIODE_P, 35 TDIODE_N, 40 VDR (power), 42 DRGND (power), 51 VDR (power), 53 DRGND (power), 62 VDR (power), 63 NC, 64 DRGND (power), 73 VDR (power), 74 DRGND (power), 87 DRGND (power), 88 VDR (power), 97 DRGND (power), 98 NC, 99 VDR (power), 108 DRGND (power), 109 NC, 110 VDR (power), 119 DRGND (power), 120 NC, 121 VDR (power), 128 VA (power), 129 DAP (power)

## ADC08L060CIMT
designator U?
8-Bit, 10 MSPS to 60 MSPS, 0.65 mW/MSPS A/D Converter with Internal Sample-and-Hold; PartNumber: ADC08L060CIMT; Manufacturer: National Semiconductor; CompType: ADC IC; PackageTopMarking: NSUZXYTT*ADC08L060*CIMT; PowerWise: N
footprint MTC24_N (TSOP, 24-Leads, Body 7.8x4.4mm, Pitch 0.65mm, IPC Medium Density)
footprint MTC24_L (TSOP, 24-Leads, Body 7.8x4.4mm, Pitch 0.65mm, IPC High Density)
footprint MTC24_M (TSOP, 24-Leads, Body 7.8x4.4mm, Pitch 0.65mm, IPC Low Density)
pins: 1 VA (power), 2 AGND (power), 3 VRT (in), 4 VA (power), 5 AGND (power), 6 VIN (in), 7 VIN GND (power), 8 AGND (power), 9 VRM (in), 10 VRB (in), 11 AGND (power), 12 VA (power), 13 D7 (out), 14 D6 (out), 15 D5 (out), 16 D4 (out), 17 DR GND (power), 18 VDR (power), 19 D3 (out), 20 D2 (out), 21 D1 (out), 22 D0 (out), 23 PD (in), 24 CLK (in)

## ADC10D020CIVS
designator U?
Dual 10-Bit, 20MSPS, 150mW A/D Converter; PartNumber: ADC10D020CIVS; Manufacturer: National Semiconductor; CompType: ADC IC; PackageTopMarking: NSUZXYTT*10D020*CIVS; PowerWise: N
footprint VBC48A_N (Thin QFP, 48-Leads, Body 7x7mm, Pitch 0.5mm, IPC Medium Density)
footprint VBC48A_L (Thin QFP, 48-Leads, Body 7x7mm, Pitch 0.5mm, IPC High Density)
footprint VBC48A_M (Thin QFP, 48-Leads, Body 7x7mm, Pitch 0.5mm, IPC Low Density)
pins: 1 VREF (power), 2 OS (in), 3 AGND (power), 4 VD (power), 5 DGND (power), 6 VDR (power), 7 DRGND (power), 8 I9 (out), 9 I8 (out), 10 I7 (out), 11 I6 (out), 12 I5 (out), 13 I4 (out), 14 I3 (out), 15 I2 (out), 16 I1 (out), 17 I0 (out), 18 Q9 (out), 19 Q8 (out), 20 Q7 (out), 21 Q6 (out), 22 Q5 (out), 23 Q4 (out), 24 Q3 (out), 25 Q2 (out), 26 Q1 (out), 27 Q0 (out), 28 I/~{Q} (out), 29 DRGND (power), 30 VDR (power), 31 OC (in), 32 OF (in), 33 CLK (in), 34 STBY (in), 35 PD (in), 36 GAIN (in), 37 Q+ (in), 38 Q- (in), 39 AGND (power), 40 VA (power), 41 VA (power), 42 AGND (power), 43 VRP, 44 VRN, 45 VCMO (out), 46 AGND (power), 47 I- (in), 48 I+ (in)

## ADC10D040CIVS
designator U?
Dual 10-Bit, 40 MSPS, 267 mW A/D Converter; PartNumber: ADC10D040CIVS; Manufacturer: National Semiconductor; CompType: ADC IC; PackageTopMarking: NSUZXYTT*10D040*CIVS; PowerWise: N
footprint VBC48A_N (Thin QFP, 48-Leads, Body 7x7mm, Pitch 0.5mm, IPC Medium Density)
footprint VBC48A_L (Thin QFP, 48-Leads, Body 7x7mm, Pitch 0.5mm, IPC High Density)
footprint VBC48A_M (Thin QFP, 48-Leads, Body 7x7mm, Pitch 0.5mm, IPC Low Density)
pins: 1 VREF (power), 2 OS (in), 3 AGND (power), 4 VD (power), 5 DGND (power), 6 VDR (power), 7 DRGND (power), 8 I9 (out), 9 I8 (out), 10 I7 (out), 11 I6 (out), 12 I5 (out), 13 I4 (out), 14 I3 (out), 15 I2 (out), 16 I1 (out), 17 I0 (out), 18 Q9 (out), 19 Q8 (out), 20 Q7 (out), 21 Q6 (out), 22 Q5 (out), 23 Q4 (out), 24 Q3 (out), 25 Q2 (out), 26 Q1 (out), 27 Q0 (out), 28 I/~{Q} (out), 29 DRGND (power), 30 VDR (power), 31 OC (in), 32 OF (in), 33 CLK (in), 34 STBY (in), 35 PD (in), 36 GAIN (in), 37 Q+ (in), 38 Q- (in), 39 AGND (power), 40 VA (power), 41 VA (power), 42 AGND (power), 43 VRP, 44 VRN, 45 VCMO (out), 46 AGND (power), 47 I- (in), 48 I+ (in)

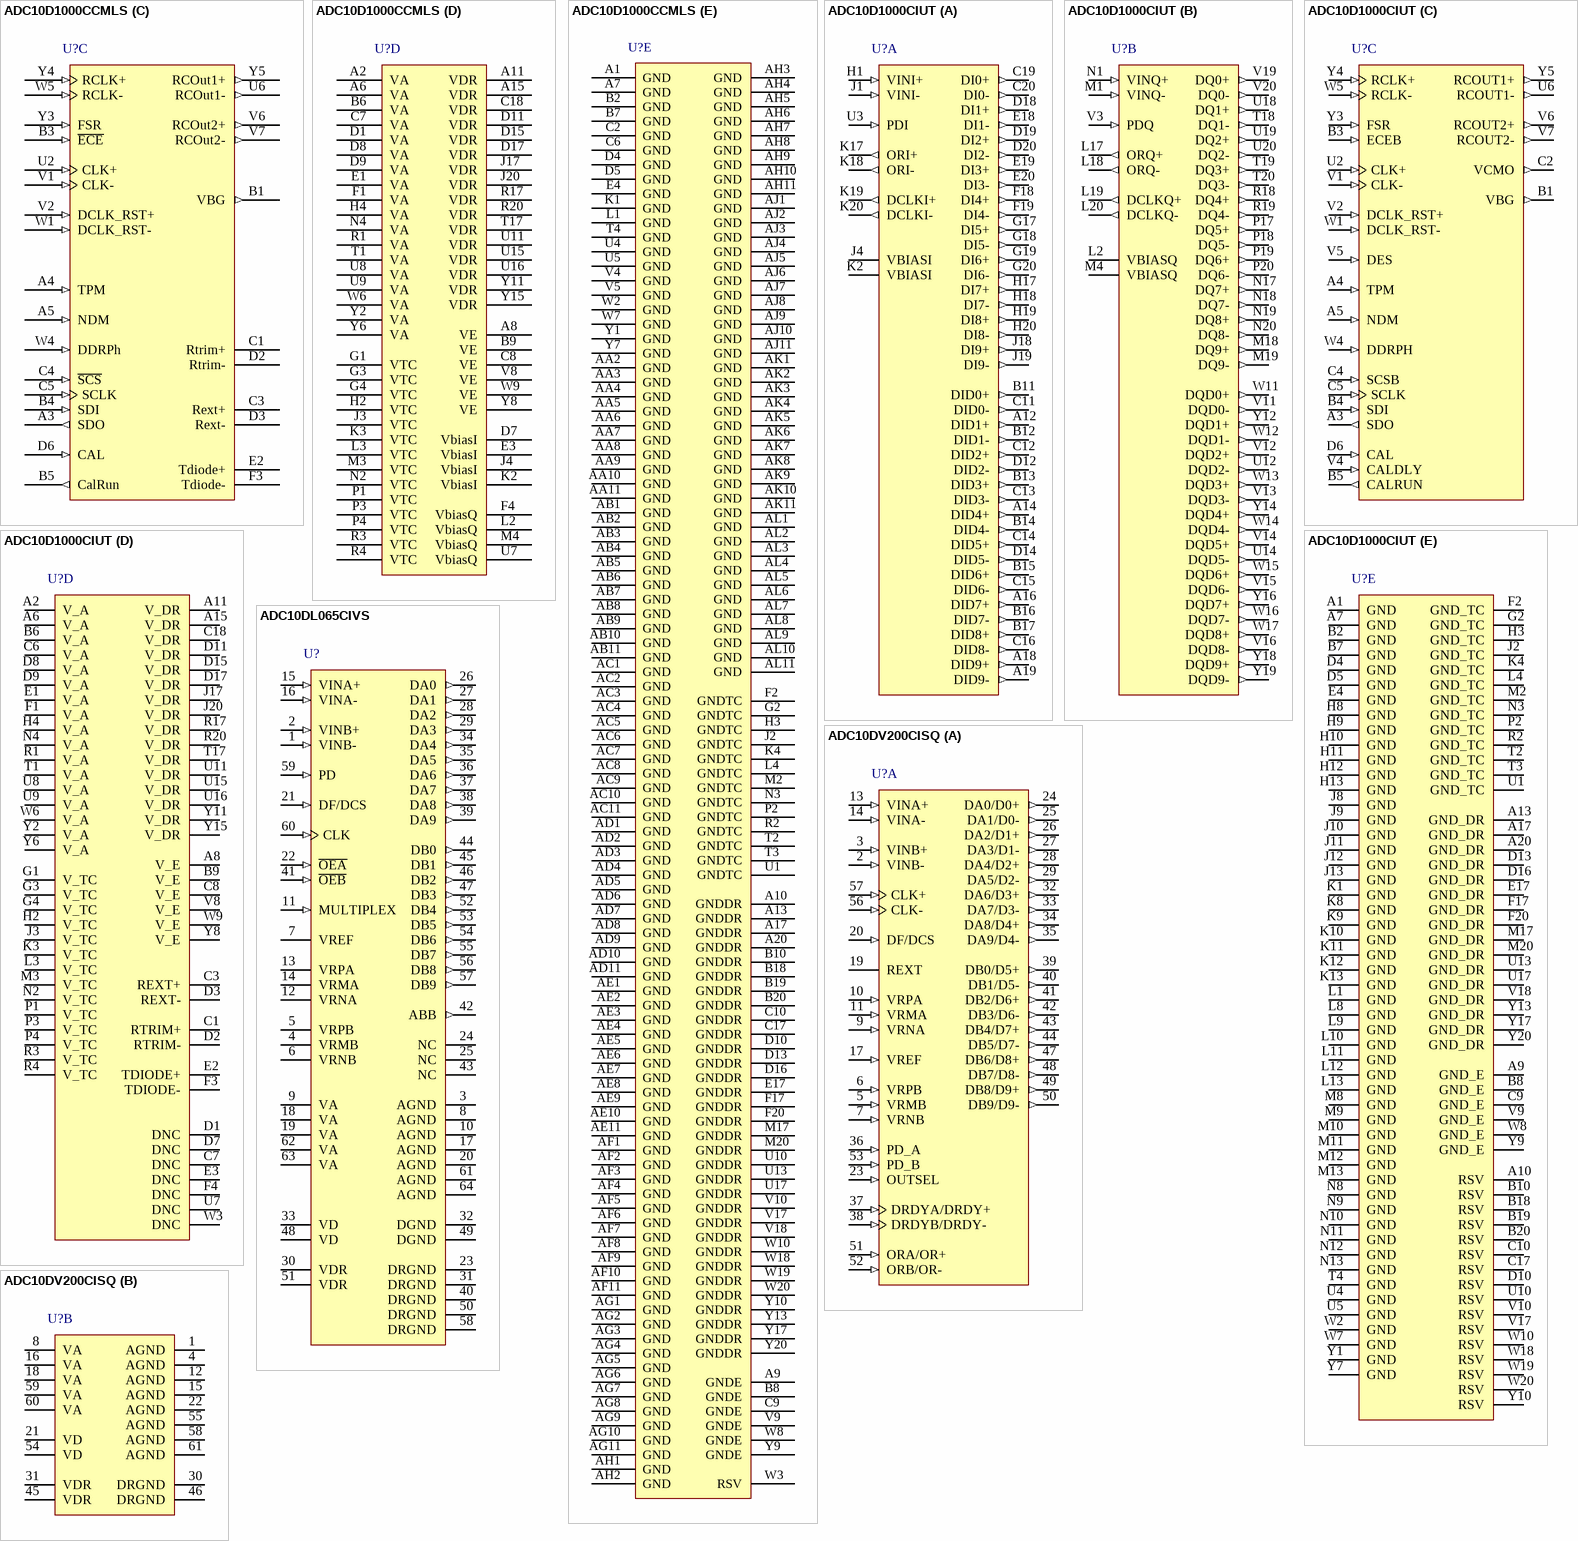
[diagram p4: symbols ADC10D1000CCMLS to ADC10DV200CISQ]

## ADC10D1000CCMLS
designator U?
Low Power, 10-Bit, Dual 1.0 GSPS or Single 2.0 GSPS A/D Converter; PartNumber: ADC10D1000CCMLS; Manufacturer: National Semiconductor; CompType: ADC IC; PackageTopMarking: NSZSSXXYYA*ADC10D1000CC*MLS; PowerWise: Y; MilaeroCode: EXX
footprint CCC376A (CGA, 376-Leads, Body 27.9x27.9mm, Pitch 1.27 & 1.0mm, NSC Recommended Pads)
part A pins: A12 DId1+ (out), A14 DId4+ (out), A16 DId7+ (out), A18 DId9+ (out), A19 DId9- (out), B11 DId0+ (out), B12 DId1- (out), B13 DId3+ (out), B14 DId4- (out), B15 DId6+ (out), B16 DId7- (out), B17 DId8+ (out), C11 DId0- (out), C12 DId2+ (out), C13 DId3- (out), C14 DId5+ (out), C15 DId6- (out), C16 DId8- (out), C19 DI0+ (out), C20 DI0- (out), D12 DId2- (out), D14 DId5- (out), D18 DI1+ (out), D19 DI2+ (out), D20 DI2- (out), E18 DI1- (out), E19 DI3+ (out), E20 DI3- (out), F18 DI4+ (out), F19 DI4- (out), G17 DI5+ (out), G18 DI5- (out), G19 DI6+ (out), G20 DI6- (out), H1 VinI+ (in), H17 DI7+ (out), H18 DI7- (out), H19 DI8+ (out), H20 DI8- (out), J1 VinI- (in), J18 DI9+ (out), J19 DI9- (out), K17 ORI+ (out), K18 ORI- (out), K19 DCLKI+ (out), K20 DCLKI- (out), U3 PDI (in)
part B pins: L17 ORQ+ (out), L18 ORQ- (out), L19 DCLKQ+ (out), L20 DCLKQ- (out), M1 VinQ- (in), M18 DQ9+ (out), M19 DQ9- (out), N1 VinQ+ (in), N17 DQ7+ (out), N18 DQ7- (out), N19 DQ8+ (out), N20 DQ8- (out), P17 DQ5+ (out), P18 DQ5- (out), P19 DQ6+ (out), P20 DQ6- (out), R18 DQ4+ (out), R19 DQ4- (out), T18 DQ1- (out), T19 DQ3+ (out), T20 DQ3- (out), U12 DQd2- (out), U14 DQd5- (out), U18 DQ1+ (out), U19 DQ2+ (out), U20 DQ2- (out), V3 PDQ (in), V11 DQd0- (out), V12 DQd2+ (out), V13 DQd3- (out), V14 DQd5+ (out), V15 DQd6- (out), V16 DQd8- (out), V19 DQ0+ (out), V20 DQ0- (out), W11 DQd0+ (out), W12 DQd1- (out), W13 DQd3+ (out), W14 DQd4- (out), W15 DQd6+ (out), W16 DQd7- (out), W17 DQd8+ (out), Y12 DQd1+ (out), Y14 DQd4+ (out), Y16 DQd7+ (out), Y18 DQd9+ (out), Y19 DQd9- (out)
part C pins: A3 SDO (out), A4 TPM (in), A5 NDM (in), B1 VBG (out), B3 ~{ECE} (in), B4 SDI (in), B5 CalRun (out), C1 Rtrim+, C3 Rext+, C4 ~{SCS} (in), C5 SCLK (in), D2 Rtrim-, D3 Rext-, D6 CAL (in), E2 Tdiode+, F3 Tdiode-, U2 CLK+ (in), U6 RCOut1- (out), V1 CLK- (in), V2 DCLK_RST+ (in), V6 RCOut2+ (out), V7 RCOut2- (out), W1 DCLK_RST- (in), W4 DDRPh (in), W5 RCLK- (in), Y3 FSR (in), Y4 RCLK+ (in), Y5 RCOut1+ (out)
part D pins: A2 VA (power), A6 VA (power), A8 VE (power), A11 VDR (power), A15 VDR (power), B6 VA (power), B9 VE (power), C7 VA (power), C8 VE (power), C18 VDR (power), D1 VA (power), D7 VbiasI, D8 VA (power), D9 VA (power), D11 VDR (power), D15 VDR (power), D17 VDR (power), E1 VA (power), E3 VbiasI, F1 VA (power), F4 VbiasQ, G1 VTC (power), G3 VTC (power), G4 VTC (power), H2 VTC (power), H4 VA (power), J3 VTC (power), J4 VbiasI, J17 VDR (power), J20 VDR (power), K2 VbiasI, K3 VTC (power), L2 VbiasQ, L3 VTC (power), M3 VTC (power), M4 VbiasQ, N2 VTC (power), N4 VA (power), P1 VTC (power), P3 VTC (power), P4 VTC (power), R1 VA (power), R3 VTC (power), R4 VTC (power), R17 VDR (power), R20 VDR (power), T1 VA (power), T17 VDR (power), U7 VbiasQ, U8 VA (power), U9 VA (power), U11 VDR (power), U15 VDR (power), U16 VDR (power), V8 VE (power), W6 VA (power), W9 VE (power), Y2 VA (power), Y6 VA (power), Y8 VE (power), Y11 VDR (power), Y15 VDR (power)
part E pins: A1 GND (power), A7 GND (power), A9 GNDE (power), A10 GNDDR (power), A13 GNDDR (power), A17 GNDDR (power), A20 GNDDR (power), AA2 GND (power), AA3 GND (power), AA4 GND (power), AA5 GND (power), AA6 GND (power), AA7 GND (power), AA8 GND (power), AA9 GND (power), AA10 GND (power), AA11 GND (power), AB1 GND (power), AB2 GND (power), AB3 GND (power), AB4 GND (power), AB5 GND (power), AB6 GND (power), AB7 GND (power), AB8 GND (power), AB9 GND (power), AB10 GND (power), AB11 GND (power), AC1 GND (power), AC2 GND (power), AC3 GND (power), AC4 GND (power), AC5 GND (power), AC6 GND (power), AC7 GND (power), AC8 GND (power), AC9 GND (power), AC10 GND (power), AC11 GND (power), AD1 GND (power), AD2 GND (power), AD3 GND (power), AD4 GND (power), AD5 GND (power), AD6 GND (power), AD7 GND (power), AD8 GND (power), AD9 GND (power), AD10 GND (power), AD11 GND (power), AE1 GND (power), AE2 GND (power), AE3 GND (power), AE4 GND (power), AE5 GND (power), AE6 GND (power), AE7 GND (power), AE8 GND (power), AE9 GND (power), AE10 GND (power), AE11 GND (power), AF1 GND (power), AF2 GND (power), AF3 GND (power), AF4 GND (power), AF5 GND (power), AF6 GND (power), AF7 GND (power), AF8 GND (power), AF9 GND (power), AF10 GND (power), AF11 GND (power), AG1 GND (power), AG2 GND (power), AG3 GND (power), AG4 GND (power), AG5 GND (power), AG6 GND (power), AG7 GND (power), AG8 GND (power), AG9 GND (power), AG10 GND (power), AG11 GND (power), AH1 GND (power), AH2 GND (power), AH3 GND (power), AH4 GND (power), AH5 GND (power), AH6 GND (power), AH7 GND (power), AH8 GND (power), AH9 GND (power), AH10 GND (power), AH11 GND (power), AJ1 GND (power), AJ2 GND (power), AJ3 GND (power), AJ4 GND (power), AJ5 GND (power), AJ6 GND (power), AJ7 GND (power), AJ8 GND (power), AJ9 GND (power), AJ10 GND (power), AJ11 GND (power), AK1 GND (power), AK2 GND (power), AK3 GND (power), AK4 GND (power), AK5 GND (power), AK6 GND (power), AK7 GND (power), AK8 GND (power), AK9 GND (power), AK10 GND (power), AK11 GND (power), AL1 GND (power), AL2 GND (power), AL3 GND (power), AL4 GND (power), AL5 GND (power), AL6 GND (power), AL7 GND (power), AL8 GND (power), AL9 GND (power), AL10 GND (power), AL11 GND (power), B2 GND (power), B7 GND (power), B8 GNDE (power), B10 GNDDR (power), B18 GNDDR (power), B19 GNDDR (power), B20 GNDDR (power), C2 GND (power), C6 GND (power), C9 GNDE (power), C10 GNDDR (power), C17 GNDDR (power), D4 GND (power), D5 GND (power), D10 GNDDR (power), D13 GNDDR (power), D16 GNDDR (power), E4 GND (power), E17 GNDDR (power), F2 GNDTC (power), F17 GNDDR (power), F20 GNDDR (power), G2 GNDTC (power), H3 GNDTC (power), J2 GNDTC (power), K1 GND (power), K4 GNDTC (power), L1 GND (power), L4 GNDTC (power), M2 GNDTC (power), M17 GNDDR (power), M20 GNDDR (power), N3 GNDTC (power), P2 GNDTC (power), R2 GNDTC (power), T2 GNDTC (power), T3 GNDTC (power), T4 GND (power), U1 GNDTC (power), U4 GND (power), U5 GND (power), U10 GNDDR (power), U13 GNDDR (power), U17 GNDDR (power), V4 GND (power), V5 GND (power), V9 GNDE (power), V10 GNDDR (power), V17 GNDDR (power), V18 GNDDR (power), W2 GND (power), W3 RSV, W7 GND (power), W8 GNDE (power), W10 GNDDR (power), W18 GNDDR (power), W19 GNDDR (power), W20 GNDDR (power), Y1 GND (power), Y7 GND (power), Y9 GNDE (power), Y10 GNDDR (power), Y13 GNDDR (power), Y17 GNDDR (power), Y20 GNDDR (power)

## ADC10D1000CIUT
designator U?
Low Power, 10-Bit, Dual 1.0 GSPS or Single 2.0 GSPS A/D Converter; PartNumber: ADC10D1000CIUT; Manufacturer: National Semiconductor; CompType: ADC IC; PackageTopMarking: NSUZXYYTTE#*ADC10D1000*CIUT; PowerWise: Y
footprint UFH292A (BGA, 292-Leads, Body 27x27mm, Pitch 1.27mm)
part A pins: A12 DID1+ (out), A14 DID4+ (out), A16 DID7+ (out), A18 DID9+ (out), A19 DID9- (out), B11 DID0+ (out), B12 DID1- (out), B13 DID3+ (out), B14 DID4- (out), B15 DID6+ (out), B16 DID7- (out), B17 DID8+ (out), C11 DID0- (out), C12 DID2+ (out), C13 DID3- (out), C14 DID5+ (out), C15 DID6- (out), C16 DID8- (out), C19 DI0+ (out), C20 DI0- (out), D12 DID2- (out), D14 DID5- (out), D18 DI1+ (out), D19 DI2+ (out), D20 DI2- (out), E18 DI1- (out), E19 DI3+ (out), E20 DI3- (out), F18 DI4+ (out), F19 DI4- (out), G17 DI5+ (out), G18 DI5- (out), G19 DI6+ (out), G20 DI6- (out), H1 VINI+ (in), H17 DI7+ (out), H18 DI7- (out), H19 DI8+ (out), H20 DI8- (out), J1 VINI- (in), J4 VBIASI (power), J18 DI9+ (out), J19 DI9- (out), K2 VBIASI (power), K17 ORI+ (out), K18 ORI- (out), K19 DCLKI+ (out), K20 DCLKI- (out), U3 PDI (in)
part B pins: L2 VBIASQ (power), L17 ORQ+ (out), L18 ORQ- (out), L19 DCLKQ+ (out), L20 DCLKQ- (out), M1 VINQ- (in), M4 VBIASQ (power), M18 DQ9+ (out), M19 DQ9- (out), N1 VINQ+ (in), N17 DQ7+ (out), N18 DQ7- (out), N19 DQ8+ (out), N20 DQ8- (out), P17 DQ5+ (out), P18 DQ5- (out), P19 DQ6+ (out), P20 DQ6- (out), R18 DQ4+ (out), R19 DQ4- (out), T18 DQ1- (out), T19 DQ3+ (out), T20 DQ3- (out), U12 DQD2- (out), U14 DQD5- (out), U18 DQ1+ (out), U19 DQ2+ (out), U20 DQ2- (out), V3 PDQ (in), V11 DQD0- (out), V12 DQD2+ (out), V13 DQD3- (out), V14 DQD5+ (out), V15 DQD6- (out), V16 DQD8- (out), V19 DQ0+ (out), V20 DQ0- (out), W11 DQD0+ (out), W12 DQD1- (out), W13 DQD3+ (out), W14 DQD4- (out), W15 DQD6+ (out), W16 DQD7- (out), W17 DQD8+ (out), Y12 DQD1+ (out), Y14 DQD4+ (out), Y16 DQD7+ (out), Y18 DQD9+ (out), Y19 DQD9- (out)
part C pins: A3 SDO (out), A4 TPM (in), A5 NDM (in), B1 VBG (out), B3 ECEB (in), B4 SDI (in), B5 CALRUN (out), C2 VCMO (out), C4 SCSB (in), C5 SCLK (in), D6 CAL (in), U2 CLK+ (in), U6 RCOUT1- (out), V1 CLK- (in), V2 DCLK_RST+ (in), V4 CALDLY (in), V5 DES (in), V6 RCOUT2+ (out), V7 RCOUT2- (out), W1 DCLK_RST- (in), W4 DDRPH (in), W5 RCLK- (in), Y3 FSR (in), Y4 RCLK+ (in), Y5 RCOUT1+ (out)
part D pins: A2 V_A (power), A6 V_A (power), A8 V_E (power), A11 V_DR (power), A15 V_DR (power), B6 V_A (power), B9 V_E (power), C1 RTRIM+, C3 REXT+, C6 V_A (power), C7 DNC, C8 V_E (power), C18 V_DR (power), D1 DNC, D2 RTRIM-, D3 REXT-, D7 DNC, D8 V_A (power), D9 V_A (power), D11 V_DR (power), D15 V_DR (power), D17 V_DR (power), E1 V_A (power), E2 TDIODE+, E3 DNC, F1 V_A (power), F3 TDIODE-, F4 DNC, G1 V_TC (power), G3 V_TC (power), G4 V_TC (power), H2 V_TC (power), H4 V_A (power), J3 V_TC (power), J17 V_DR (power), J20 V_DR (power), K3 V_TC (power), L3 V_TC (power), M3 V_TC (power), N2 V_TC (power), N4 V_A (power), P1 V_TC (power), P3 V_TC (power), P4 V_TC (power), R1 V_A (power), R3 V_TC (power), R4 V_TC (power), R17 V_DR (power), R20 V_DR (power), T1 V_A (power), T17 V_DR (power), U7 DNC, U8 V_A (power), U9 V_A (power), U11 V_DR (power), U15 V_DR (power), U16 V_DR (power), V8 V_E (power), W3 DNC, W6 V_A (power), W9 V_E (power), Y2 V_A (power), Y6 V_A (power), Y8 V_E (power), Y11 V_DR (power), Y15 V_DR (power)
part E pins: A1 GND (power), A7 GND (power), A9 GND_E (power), A10 RSV, A13 GND_DR (power), A17 GND_DR (power), A20 GND_DR (power), B2 GND (power), B7 GND (power), B8 GND_E (power), B10 RSV, B18 RSV, B19 RSV, B20 RSV, C9 GND_E (power), C10 RSV, C17 RSV, D4 GND (power), D5 GND (power), D10 RSV, D13 GND_DR (power), D16 GND_DR (power), E4 GND (power), E17 GND_DR (power), F2 GND_TC (power), F17 GND_DR (power), F20 GND_DR (power), G2 GND_TC (power), H3 GND_TC (power), H8 GND (power), H9 GND (power), H10 GND (power), H11 GND (power), H12 GND (power), H13 GND (power), J2 GND_TC (power), J8 GND (power), J9 GND (power), J10 GND (power), J11 GND (power), J12 GND (power), J13 GND (power), K1 GND (power), K4 GND_TC (power), K8 GND (power), K9 GND (power), K10 GND (power), K11 GND (power), K12 GND (power), K13 GND (power), L1 GND (power), L4 GND_TC (power), L8 GND (power), L9 GND (power), L10 GND (power), L11 GND (power), L12 GND (power), L13 GND (power), M2 GND_TC (power), M8 GND (power), M9 GND (power), M10 GND (power), M11 GND (power), M12 GND (power), M13 GND (power), M17 GND_DR (power), M20 GND_DR (power), N3 GND_TC (power), N8 GND (power), N9 GND (power), N10 GND (power), N11 GND (power), N12 GND (power), N13 GND (power), P2 GND_TC (power), R2 GND_TC (power), T2 GND_TC (power), T3 GND_TC (power), T4 GND (power), U1 GND_TC (power), U4 GND (power), U5 GND (power), U10 RSV, U13 GND_DR (power), U17 GND_DR (power), V9 GND_E (power), V10 RSV, V17 RSV, V18 GND_DR (power), W2 GND (power), W7 GND (power), W8 GND_E (power), W10 RSV, W18 RSV, W19 RSV, W20 RSV, Y1 GND (power), Y7 GND (power), Y9 GND_E (power), Y10 RSV, Y13 GND_DR (power), Y17 GND_DR (power), Y20 GND_DR (power)

## ADC10DL065CIVS
designator U?
Dual 10-Bit, 65 MSPS, 3.3V, 370mW A/D Converter; PartNumber: ADC10DL065CIVS; Manufacturer: National Semiconductor; CompType: ADC IC; PackageTopMarking: NSUZXYYTT*ADC10DL065*CIVS; PowerWise: N
footprint VEC64A_N (Thin QFP, 64-Leads, Body 10x10mm, Pitch 0.5mm, IPC Medium Density)
footprint VEC64A_L (Thin QFP, 64-Leads, Body 10x10mm, Pitch 0.5mm, IPC High Density)
footprint VEC64A_M (Thin QFP, 64-Leads, Body 10x10mm, Pitch 0.5mm, IPC Low Density)
pins: 1 VINB- (in), 2 VINB+ (in), 3 AGND (power), 4 VRMB, 5 VRPB, 6 VRNB, 7 VREF (power), 8 AGND (power), 9 VA (power), 10 AGND (power), 11 MULTIPLEX (in), 12 VRNA, 13 VRPA, 14 VRMA, 15 VINA+ (in), 16 VINA- (in), 17 AGND (power), 18 VA (power), 19 VA (power), 20 AGND (power), 21 DF/DCS (in), 22 ~{OEA} (in), 23 DRGND (power), 24 NC, 25 NC, 26 DA0 (out), 27 DA1 (out), 28 DA2 (out), 29 DA3 (out), 30 VDR (power), 31 DRGND (power), 32 DGND (power), 33 VD (power), 34 DA4 (out), 35 DA5 (out), 36 DA6 (out), 37 DA7 (out), 38 DA8 (out), 39 DA9 (out), 40 DRGND (power), 41 ~{OEB} (in), 42 ABB (out), 43 NC, 44 DB0 (out), 45 DB1 (out), 46 DB2 (out), 47 DB3 (out), 48 VD (power), 49 DGND (power), 50 DRGND (power), 51 VDR (power), 52 DB4 (out), 53 DB5 (out), 54 DB6 (out), 55 DB7 (out), 56 DB8 (out), 57 DB9 (out), 58 DRGND (power), 59 PD (in), 60 CLK (in), 61 AGND (power), 62 VA (power), 63 VA (power), 64 AGND (power)

## ADC10DV200CISQ
designator U?
Dual 10-bit, 200 MSPS Low-Power A/D Converter with Parallel LVDS/CMOS Outputs; PartNumber: ADC10DV200CISQ; Manufacturer: National Semiconductor; CompType: ADC IC; PackageTopMarking: NS*UZXYTT*10DV200*CISQ; PowerWise: Y
footprint SQA60A (QFN, 60-Leads, Body 9x9mm, Pitch 0.5mm, NSC Recommended)
part A pins: 2 VINB- (in), 3 VINB+ (in), 5 VRMB (in), 6 VRPB (in), 7 VRNB (in), 9 VRNA (in), 10 VRPA (in), 11 VRMA (in), 13 VINA+ (in), 14 VINA- (in), 17 VREF (in), 19 REXT, 20 DF/DCS (in), 23 OUTSEL (in), 24 DA0/D0+ (out), 25 DA1/D0- (out), 26 DA2/D1+ (out), 27 DA3/D1- (out), 28 DA4/D2+ (out), 29 DA5/D2- (out), 32 DA6/D3+ (out), 33 DA7/D3- (out), 34 DA8/D4+ (out), 35 DA9/D4- (out), 36 PD_A (in), 37 DRDYA/DRDY+ (in), 38 DRDYB/DRDY- (in), 39 DB0/D5+ (out), 40 DB1/D5- (out), 41 DB2/D6+ (out), 42 DB3/D6- (out), 43 DB4/D7+ (out), 44 DB5/D7- (out), 47 DB6/D8+ (out), 48 DB7/D8- (out), 49 DB8/D9+ (out), 50 DB9/D9- (out), 51 ORA/OR+ (in), 52 ORB/OR- (in), 53 PD_B (in), 56 CLK- (in), 57 CLK+ (in)
part B pins: 1 AGND (power), 4 AGND (power), 8 VA (power), 12 AGND (power), 15 AGND (power), 16 VA (power), 18 VA (power), 21 VD (power), 22 AGND (power), 30 DRGND (power), 31 VDR (power), 45 VDR (power), 46 DRGND (power), 54 VD (power), 55 AGND (power), 58 AGND (power), 59 VA (power), 60 VA (power), 61 AGND (power)

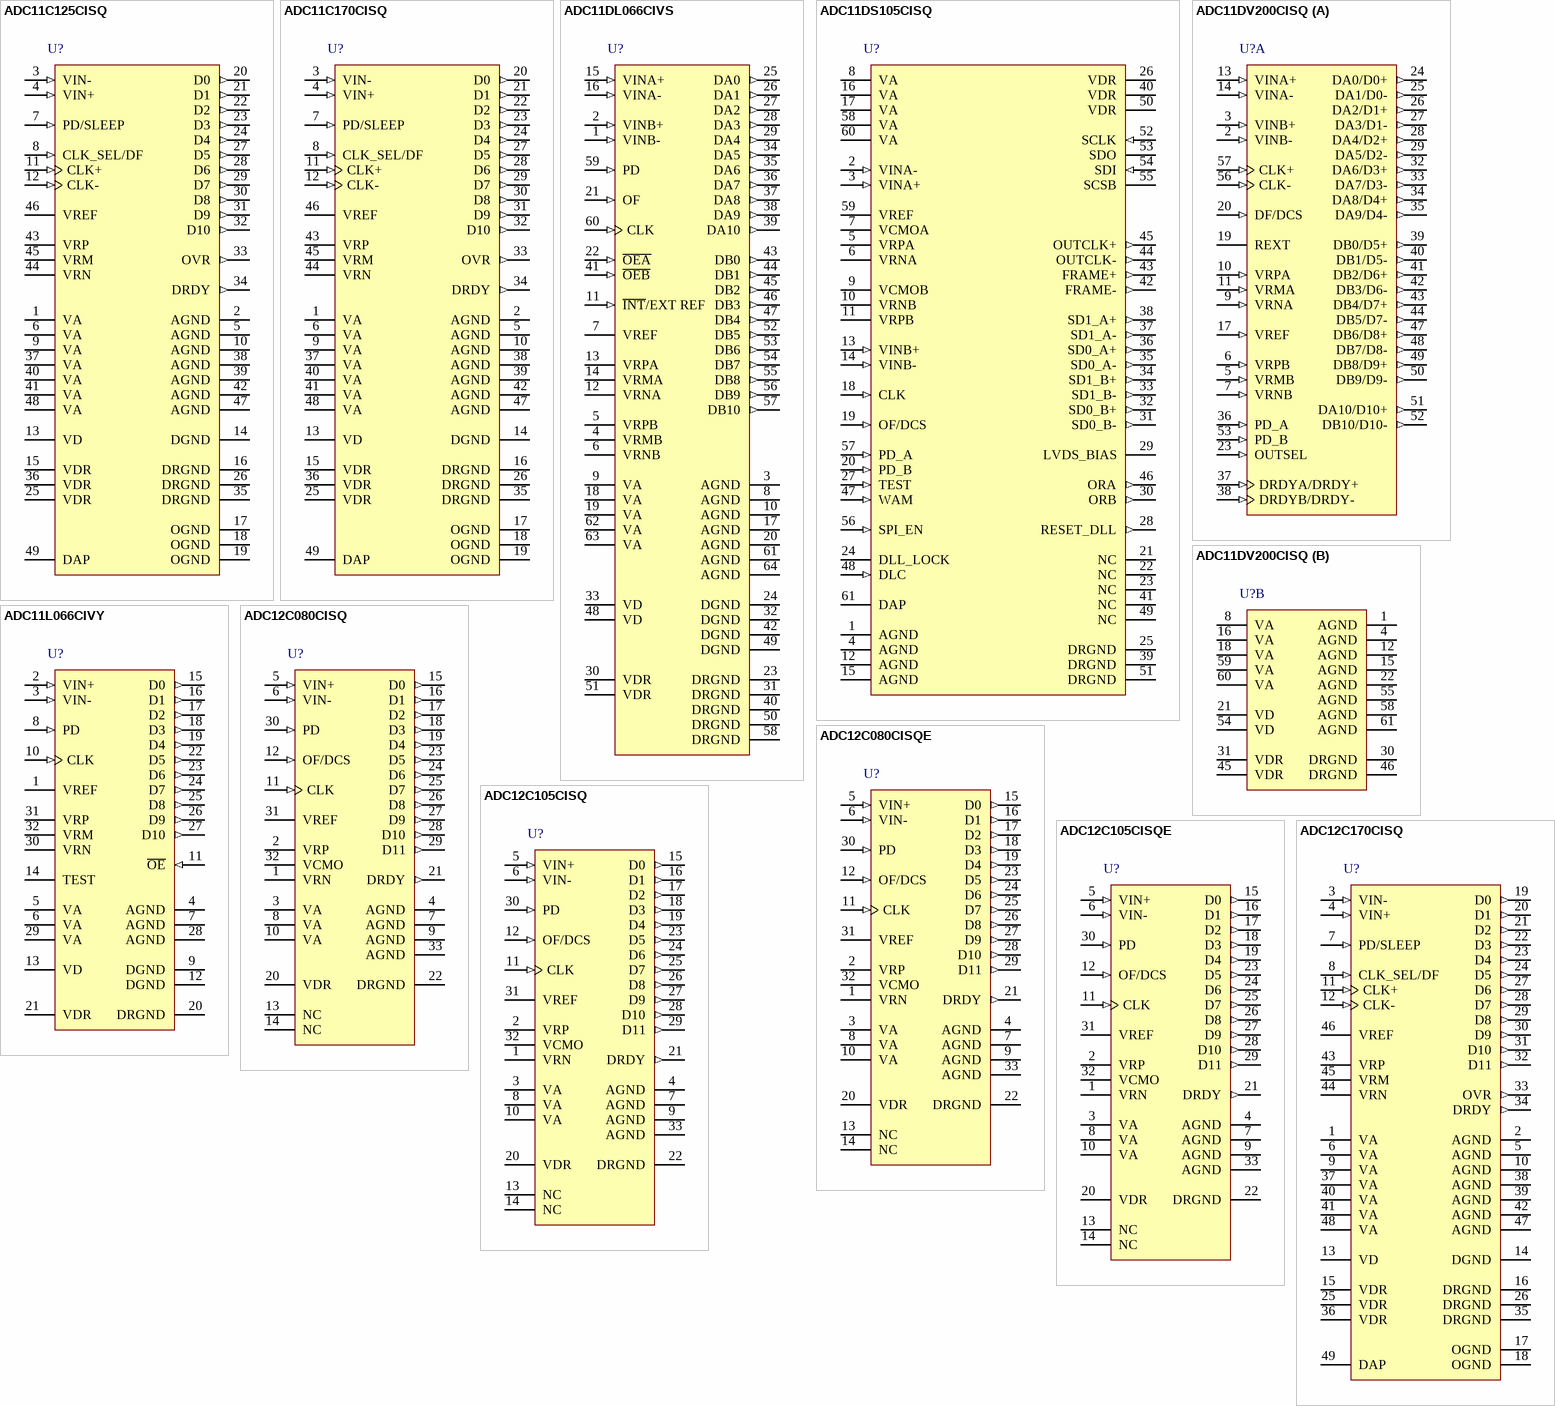
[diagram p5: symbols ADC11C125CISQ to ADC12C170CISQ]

## ADC11C125CISQ
designator U?
11-Bit, 125 MSPS, 1.1 GHz Bandwidth A/D Converter with CMOS outputs; PartNumber: ADC11C125CISQ; Manufacturer: National Semiconductor; CompType: ADC IC; PackageTopMarking: NS*UZXYTT*ADC11C125; PowerWise: N
footprint SQA48A (QFN, 48-Leads, Body 7x7mm, Pitch 0.5mm, NSC Recommended)
pins: 1 VA (power), 2 AGND (power), 3 VIN- (in), 4 VIN+ (in), 5 AGND (power), 6 VA (power), 7 PD/SLEEP (in), 8 CLK_SEL/DF (in), 9 VA (power), 10 AGND (power), 11 CLK+ (in), 12 CLK- (in), 13 VD (power), 14 DGND (power), 15 VDR (power), 16 DRGND (power), 17 OGND (power), 18 OGND (power), 19 OGND (power), 20 D0 (out), 21 D1 (out), 22 D2 (out), 23 D3 (out), 24 D4 (out), 25 VDR (power), 26 DRGND (power), 27 D5 (out), 28 D6 (out), 29 D7 (out), 30 D8 (out), 31 D9 (out), 32 D10 (out), 33 OVR (out), 34 DRDY (out), 35 DRGND (power), 36 VDR (power), 37 VA (power), 38 AGND (power), 39 AGND (power), 40 VA (power), 41 VA (power), 42 AGND (power), 43 VRP, 44 VRN, 45 VRM, 46 VREF (power), 47 AGND (power), 48 VA (power), 49 DAP (power)

## ADC11C170CISQ
designator U?
11-Bit, 170 MSPS, 1.1 GHz Bandwidth A/D Converter with CMOS outputs; PartNumber: ADC11C170CISQ; Manufacturer: National Semiconductor; CompType: ADC IC; PackageTopMarking: NS*UZXYTT*ADC11C170; PowerWise: N
footprint SQA48A (QFN, 48-Leads, Body 7x7mm, Pitch 0.5mm, NSC Recommended)
pins: 1 VA (power), 2 AGND (power), 3 VIN- (in), 4 VIN+ (in), 5 AGND (power), 6 VA (power), 7 PD/SLEEP (in), 8 CLK_SEL/DF (in), 9 VA (power), 10 AGND (power), 11 CLK+ (in), 12 CLK- (in), 13 VD (power), 14 DGND (power), 15 VDR (power), 16 DRGND (power), 17 OGND (power), 18 OGND (power), 19 OGND (power), 20 D0 (out), 21 D1 (out), 22 D2 (out), 23 D3 (out), 24 D4 (out), 25 VDR (power), 26 DRGND (power), 27 D5 (out), 28 D6 (out), 29 D7 (out), 30 D8 (out), 31 D9 (out), 32 D10 (out), 33 OVR (out), 34 DRDY (out), 35 DRGND (power), 36 VDR (power), 37 VA (power), 38 AGND (power), 39 AGND (power), 40 VA (power), 41 VA (power), 42 AGND (power), 43 VRP, 44 VRN, 45 VRM, 46 VREF (power), 47 AGND (power), 48 VA (power), 49 DAP (power)

## ADC11DL066CIVS
designator U?
Dual 11-Bit, 66 MSPS, 450 MHz Input Bandwidth A/D Converter w/Internal Reference; PartNumber: ADC11DL066CIVS; Manufacturer: National Semiconductor; CompType: ADC IC; PackageTopMarking: NSUZXYYTT*ADC11DL066*CIVS; PowerWise: N
footprint VEC64A_N (Thin QFP, 64-Leads, Body 10x10mm, Pitch 0.5mm, IPC Medium Density)
footprint VEC64A_L (Thin QFP, 64-Leads, Body 10x10mm, Pitch 0.5mm, IPC High Density)
footprint VEC64A_M (Thin QFP, 64-Leads, Body 10x10mm, Pitch 0.5mm, IPC Low Density)
pins: 1 VINB- (in), 2 VINB+ (in), 3 AGND (power), 4 VRMB, 5 VRPB, 6 VRNB, 7 VREF (power), 8 AGND (power), 9 VA (power), 10 AGND (power), 11 ~{INT}/EXT REF (in), 12 VRNA, 13 VRPA, 14 VRMA, 15 VINA+ (in), 16 VINA- (in), 17 AGND (power), 18 VA (power), 19 VA (power), 20 AGND (power), 21 OF (in), 22 ~{OEA} (in), 23 DRGND (power), 24 DGND (power), 25 DA0 (out), 26 DA1 (out), 27 DA2 (out), 28 DA3 (out), 29 DA4 (out), 30 VDR (power), 31 DRGND (power), 32 DGND (power), 33 VD (power), 34 DA5 (out), 35 DA6 (out), 36 DA7 (out), 37 DA8 (out), 38 DA9 (out), 39 DA10 (out), 40 DRGND (power), 41 ~{OEB} (in), 42 DGND (power), 43 DB0 (out), 44 DB1 (out), 45 DB2 (out), 46 DB3 (out), 47 DB4 (out), 48 VD (power), 49 DGND (power), 50 DRGND (power), 51 VDR (power), 52 DB5 (out), 53 DB6 (out), 54 DB7 (out), 55 DB8 (out), 56 DB9 (out), 57 DB10 (out), 58 DRGND (power), 59 PD (in), 60 CLK (in), 61 AGND (power), 62 VA (power), 63 VA (power), 64 AGND (power)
